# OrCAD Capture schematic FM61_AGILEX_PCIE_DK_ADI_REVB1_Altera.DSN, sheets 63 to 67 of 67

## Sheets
63 PWR - 2p5V: size B
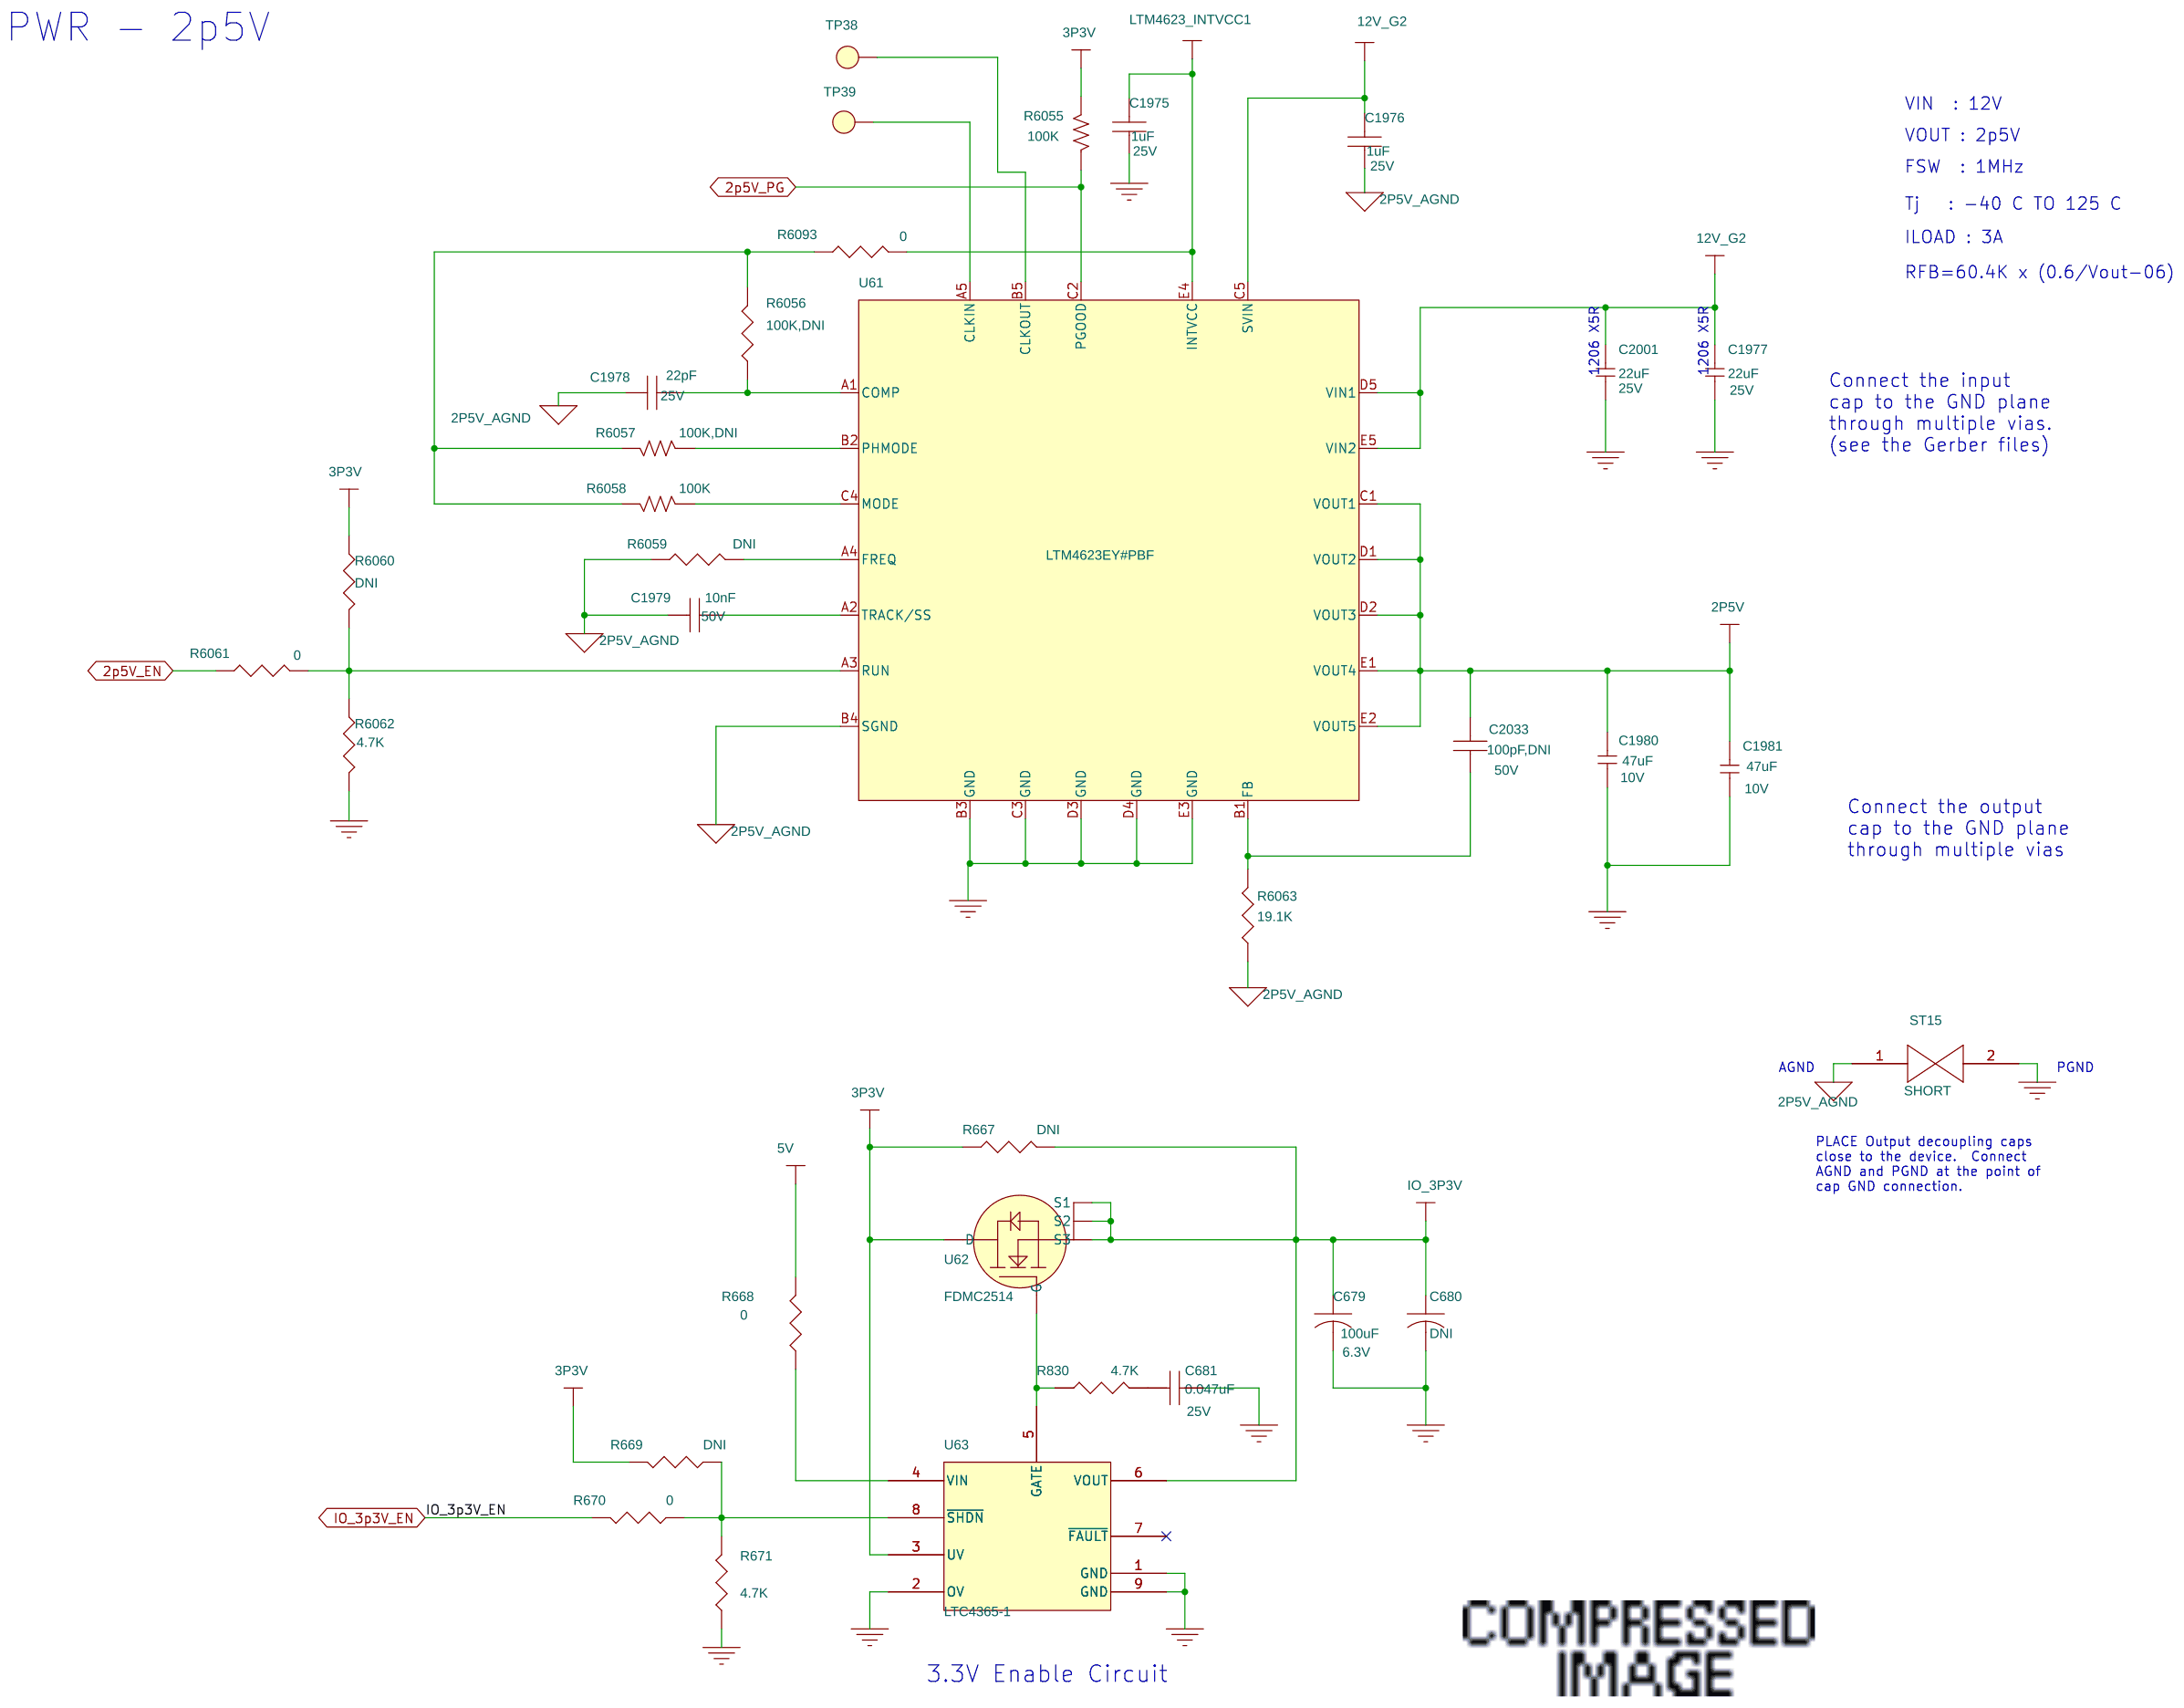
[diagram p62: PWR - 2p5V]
64 PWR - 1p1V_VCCH_GXER1: size Custom
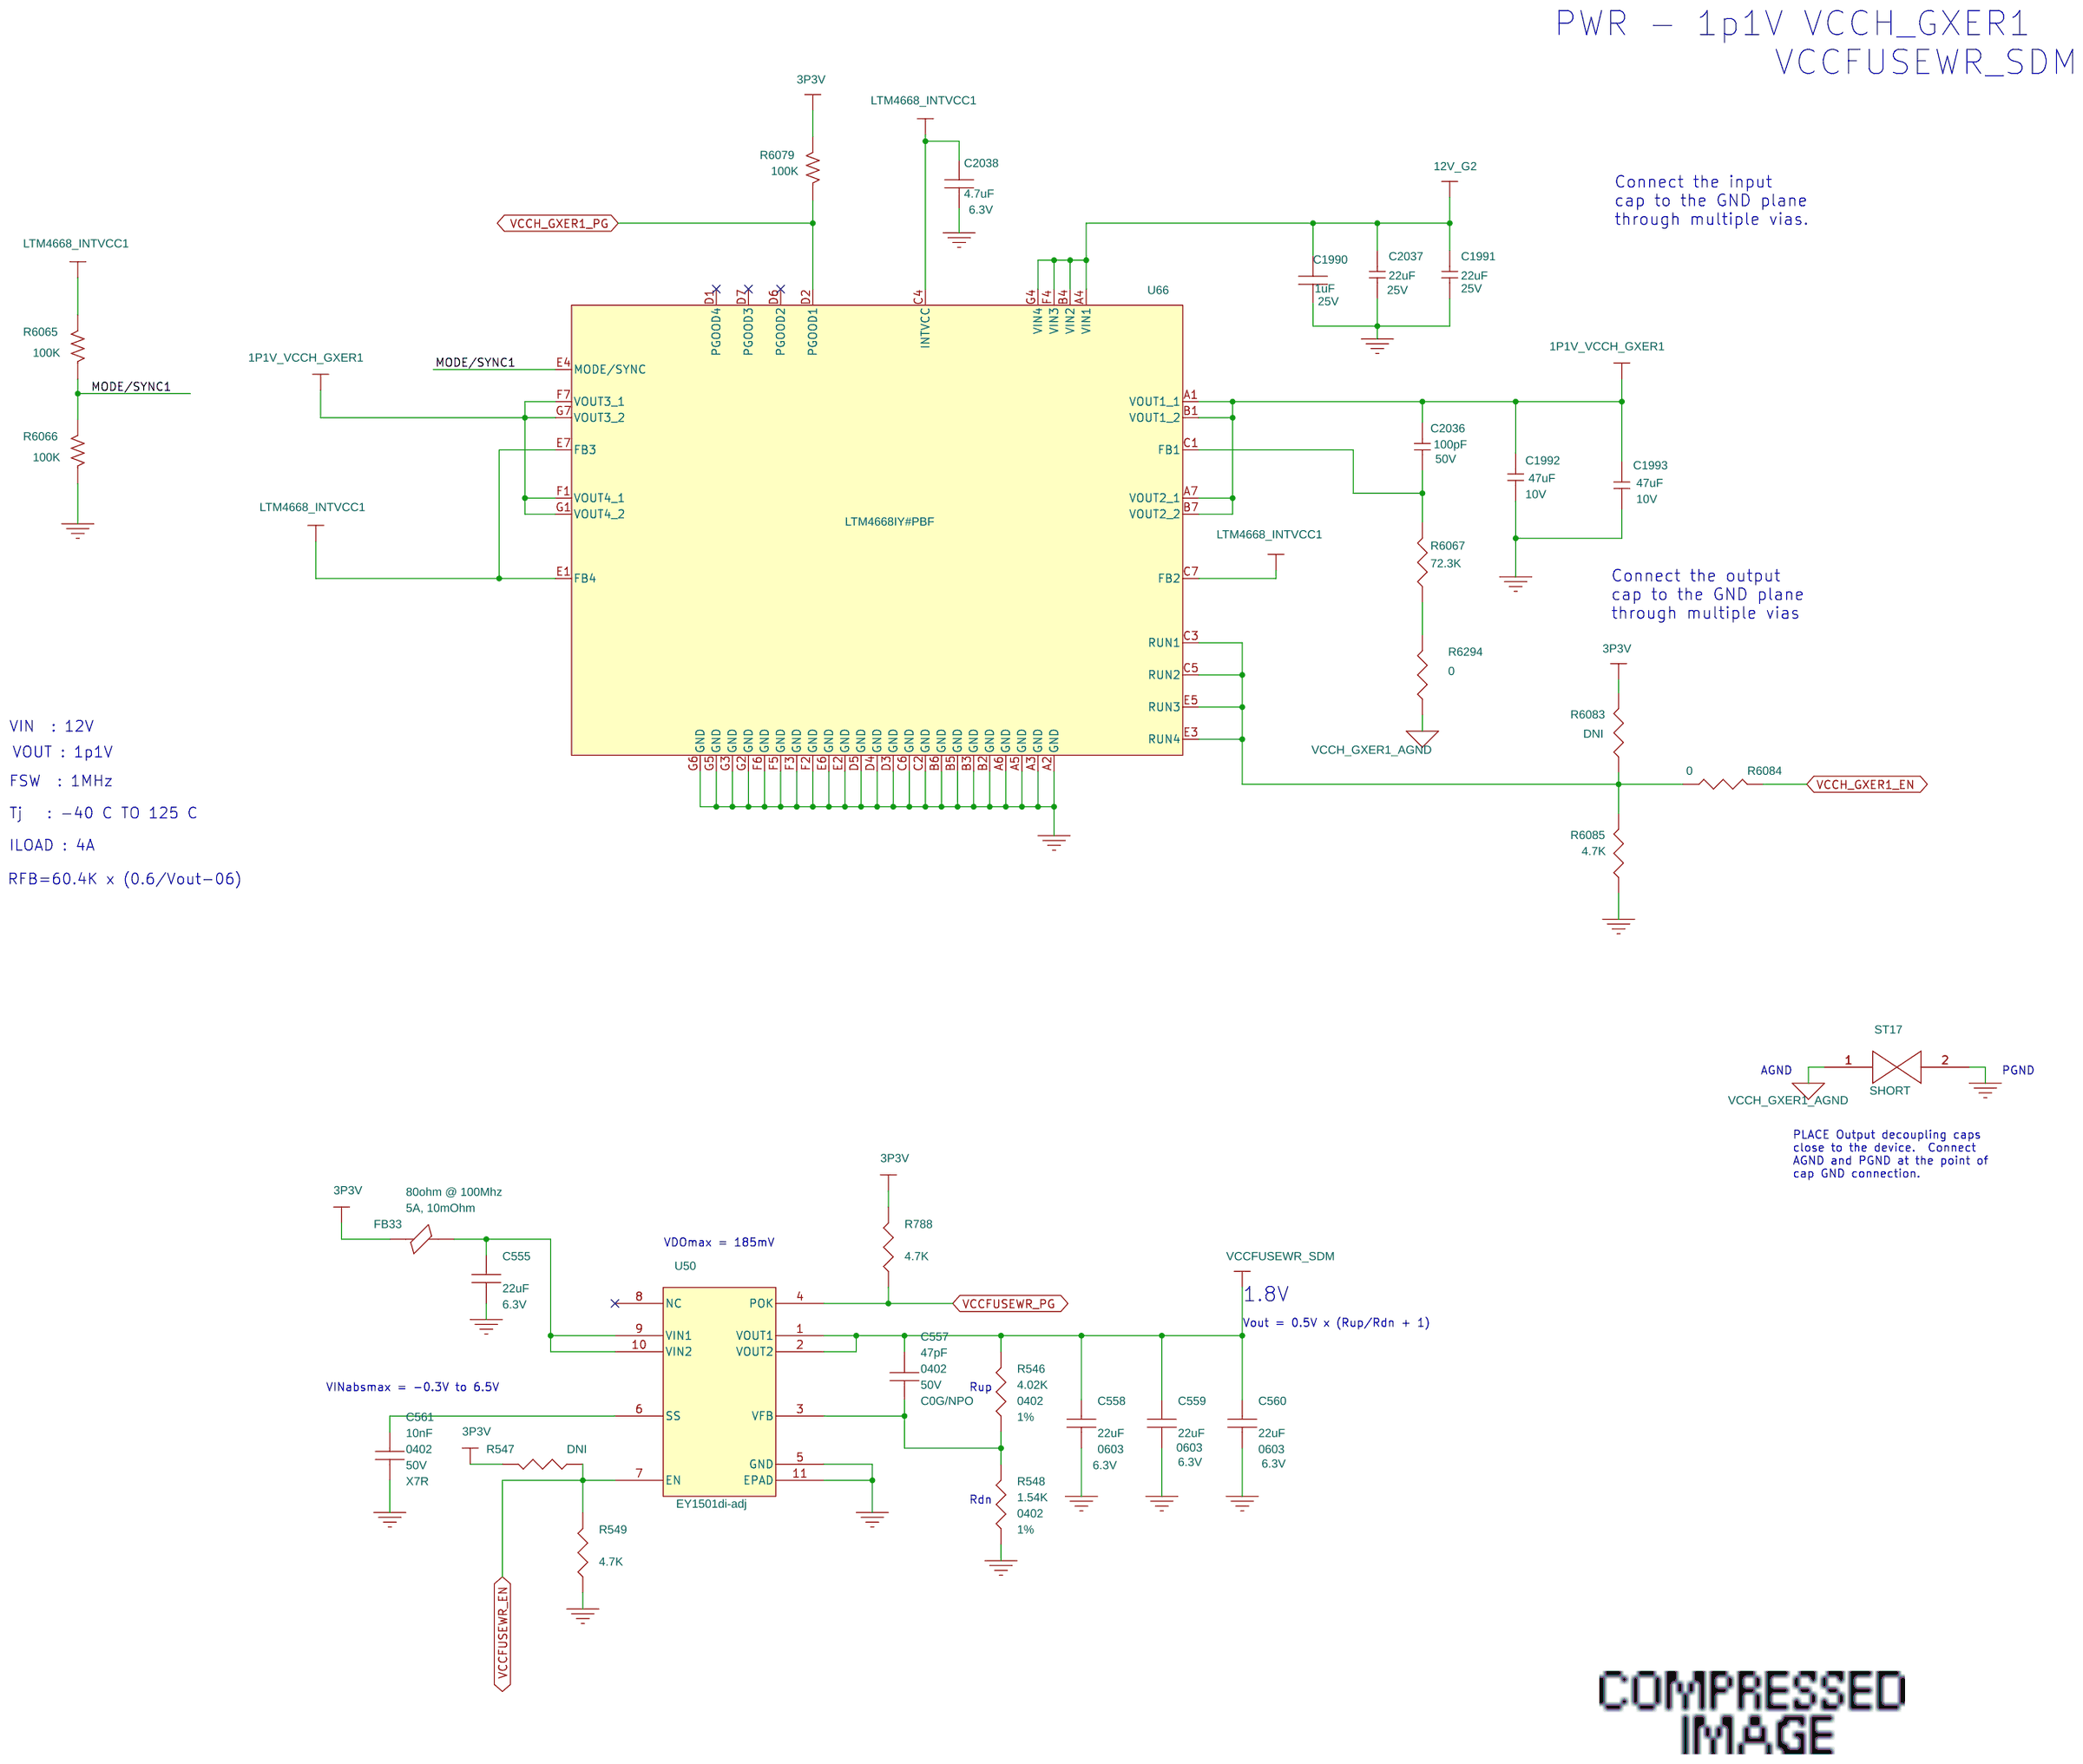
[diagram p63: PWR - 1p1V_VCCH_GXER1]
65 Decoupling Caps 1: size B
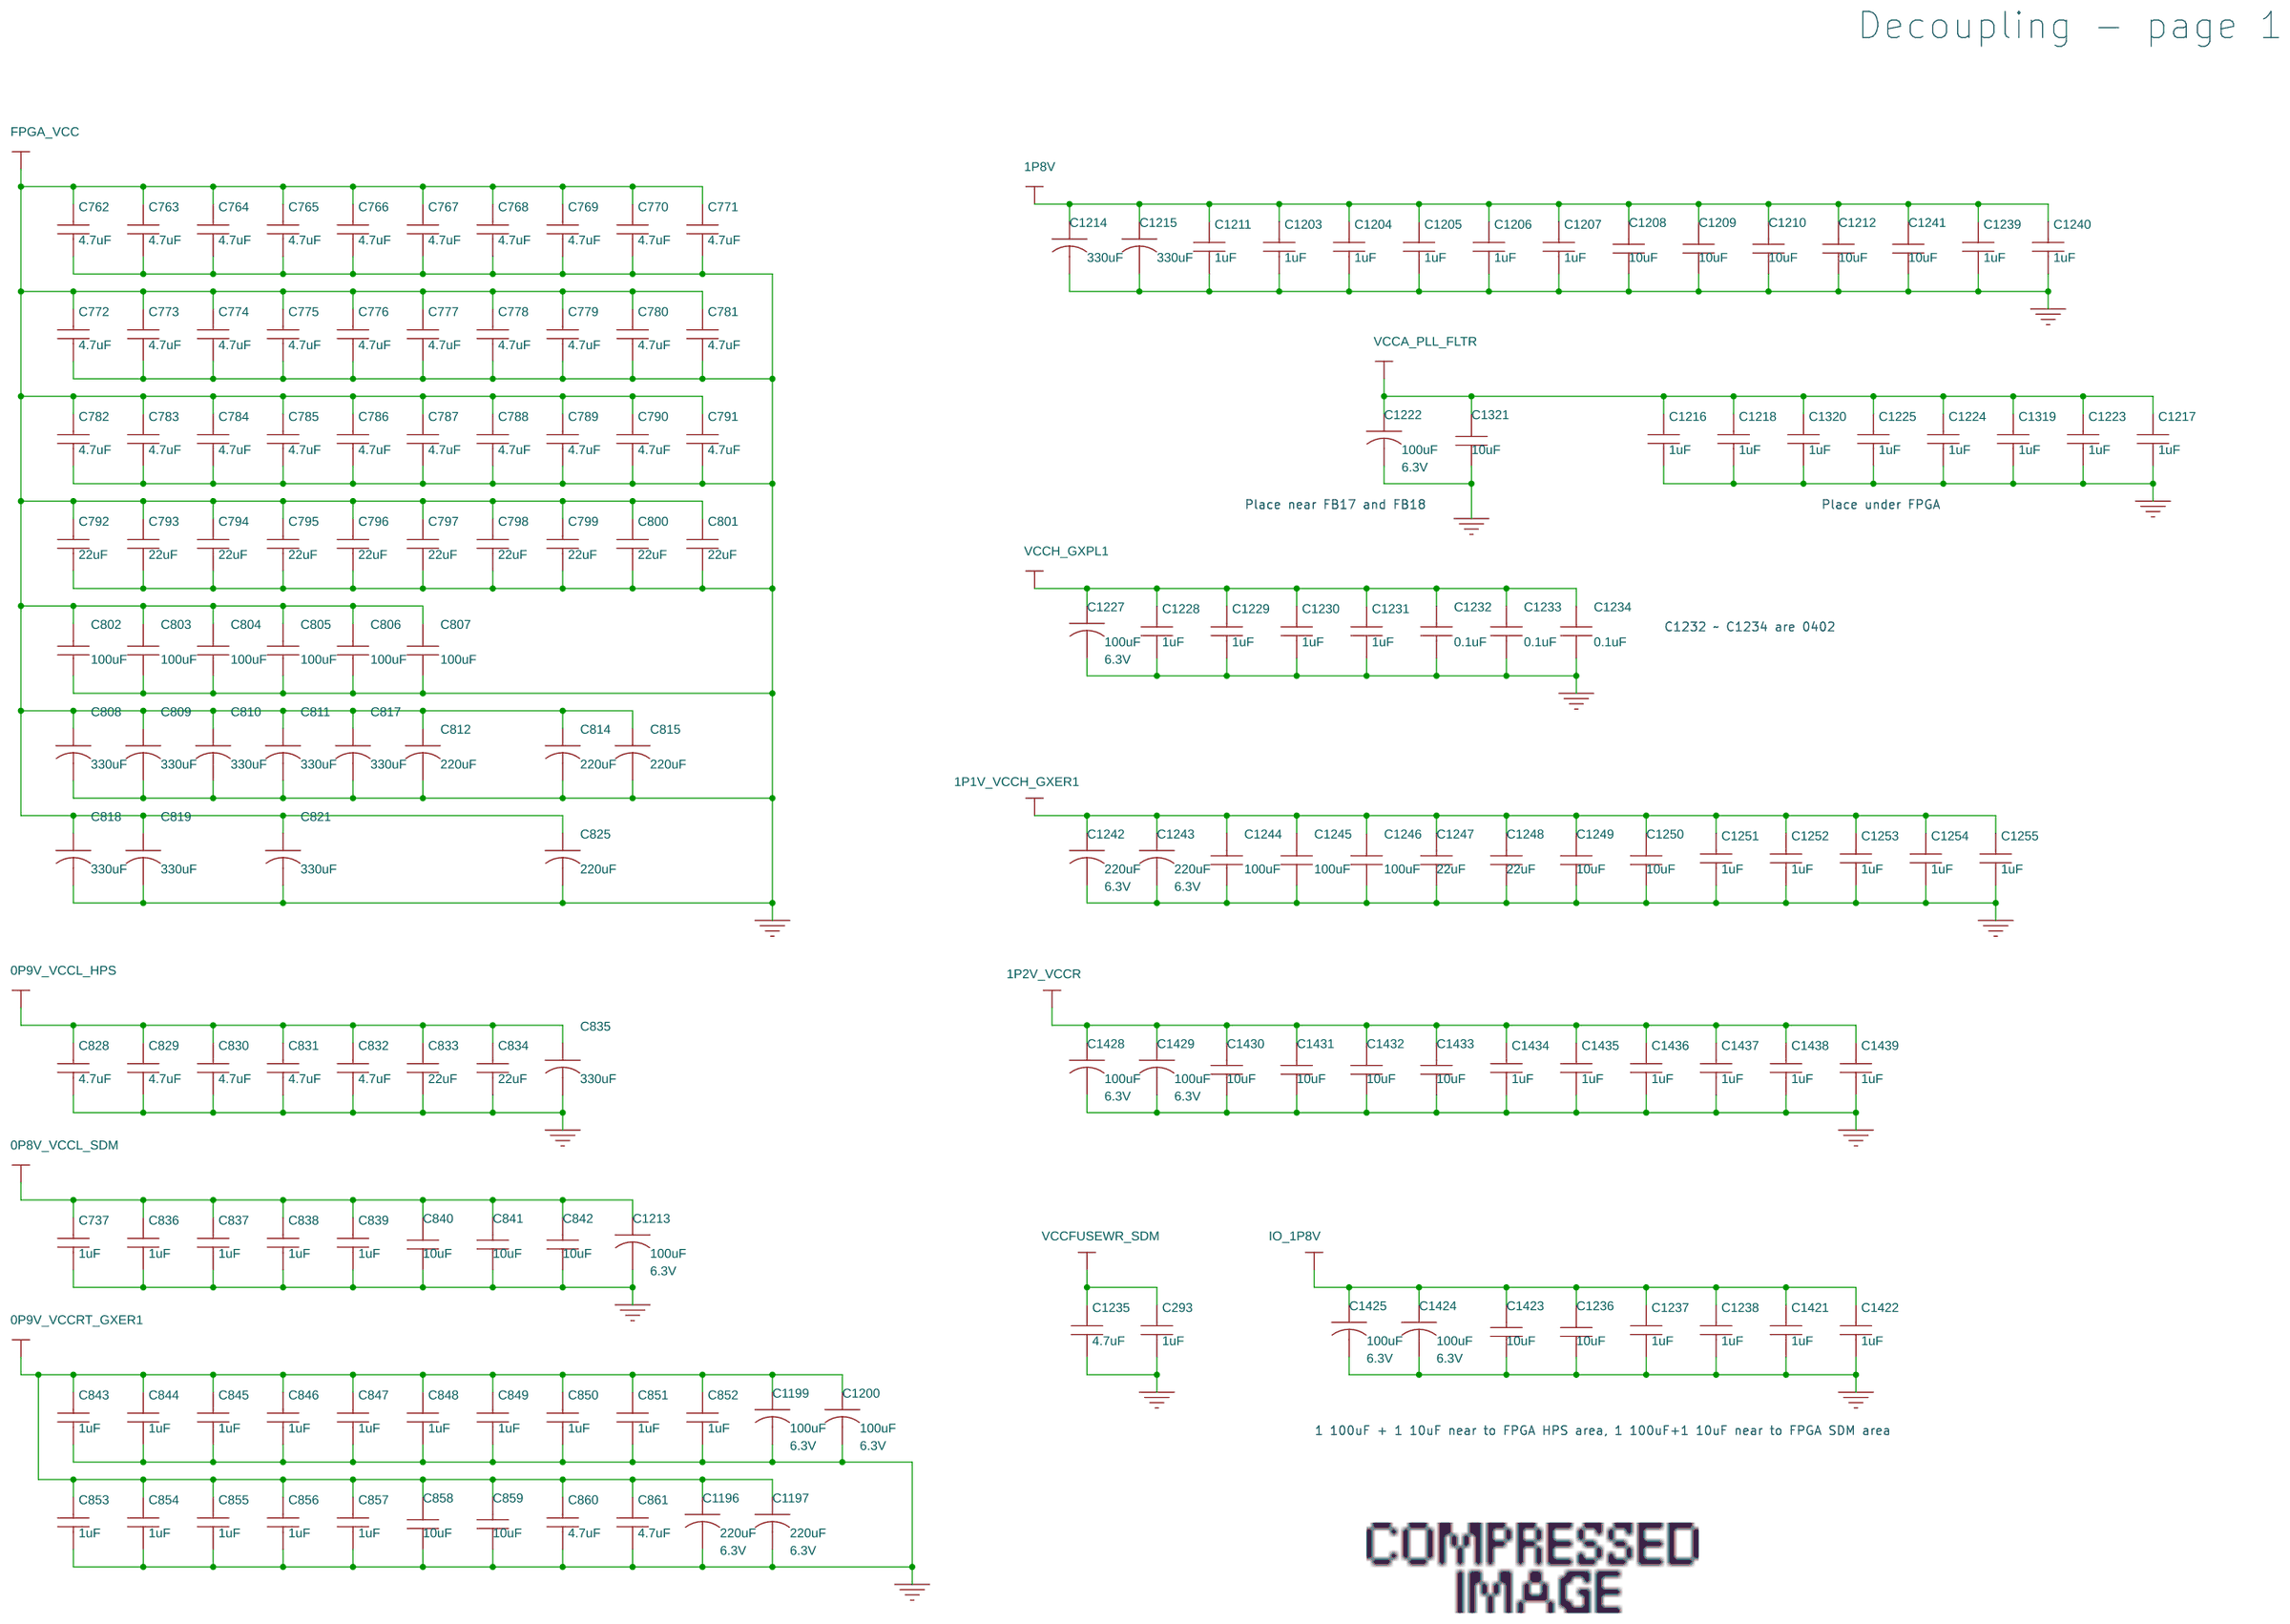
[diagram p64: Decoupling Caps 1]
66 Decoupling Caps 2: size B
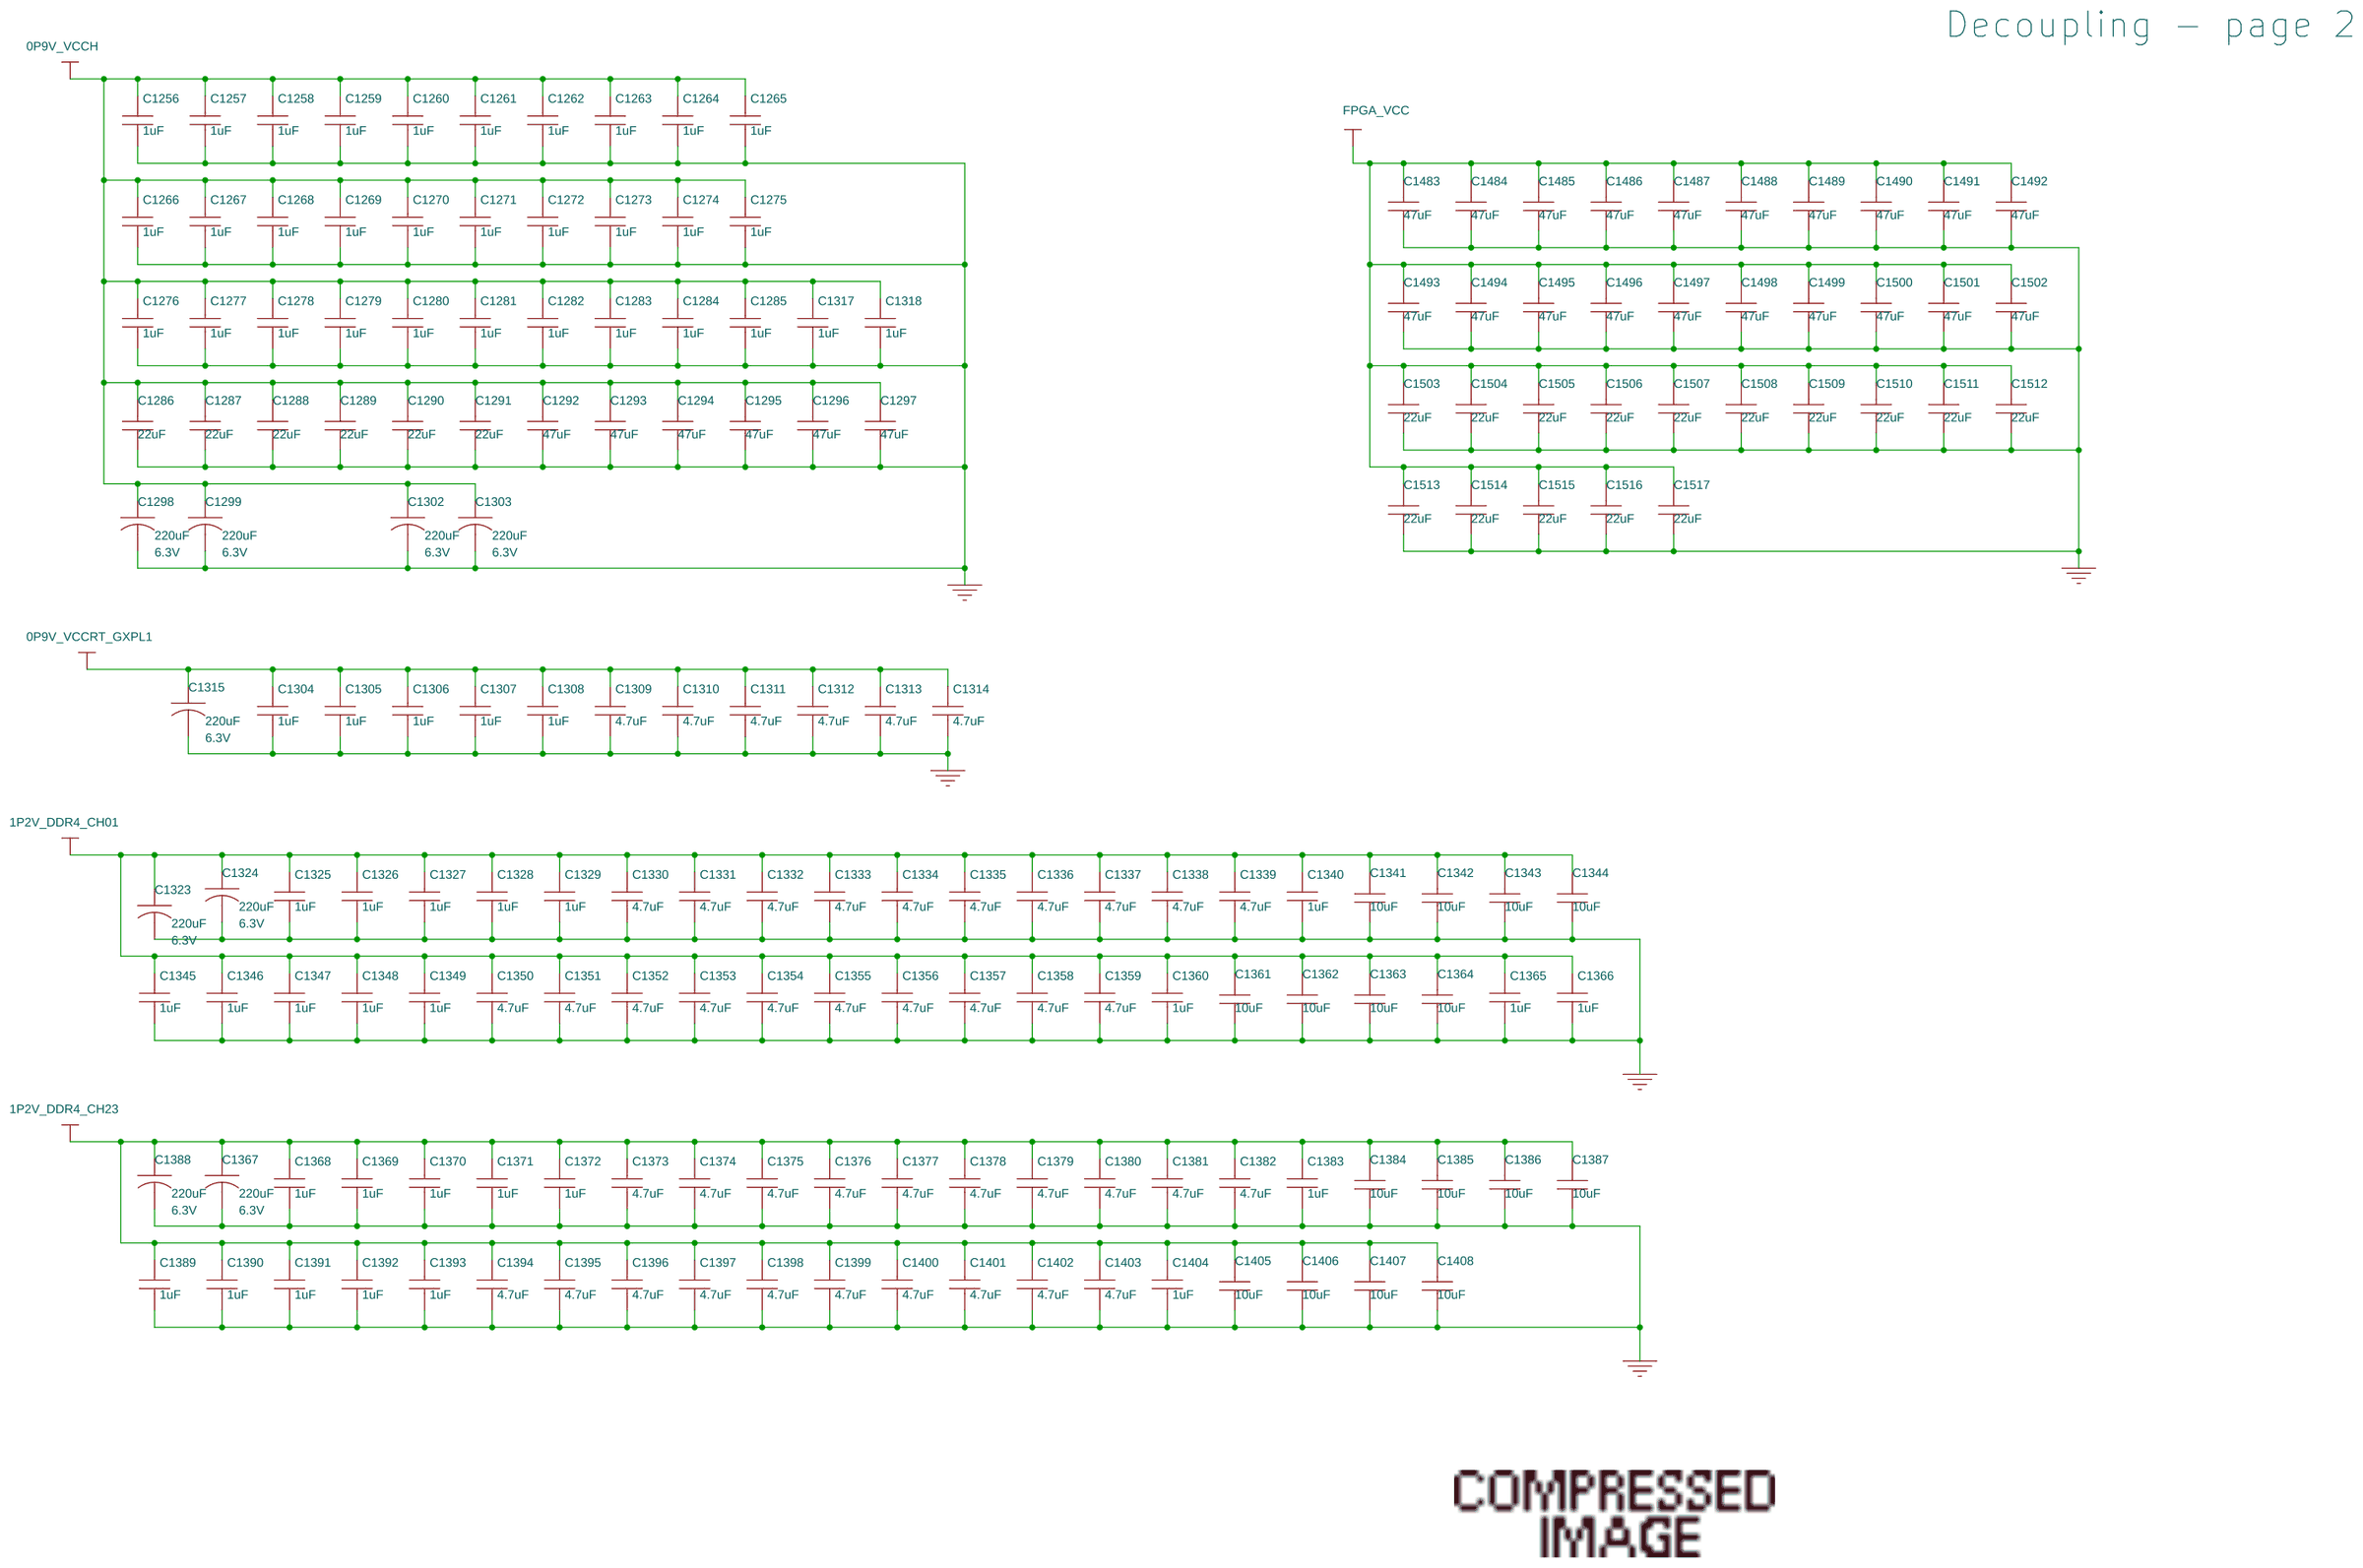
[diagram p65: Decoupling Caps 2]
67 REVISION HISTORY
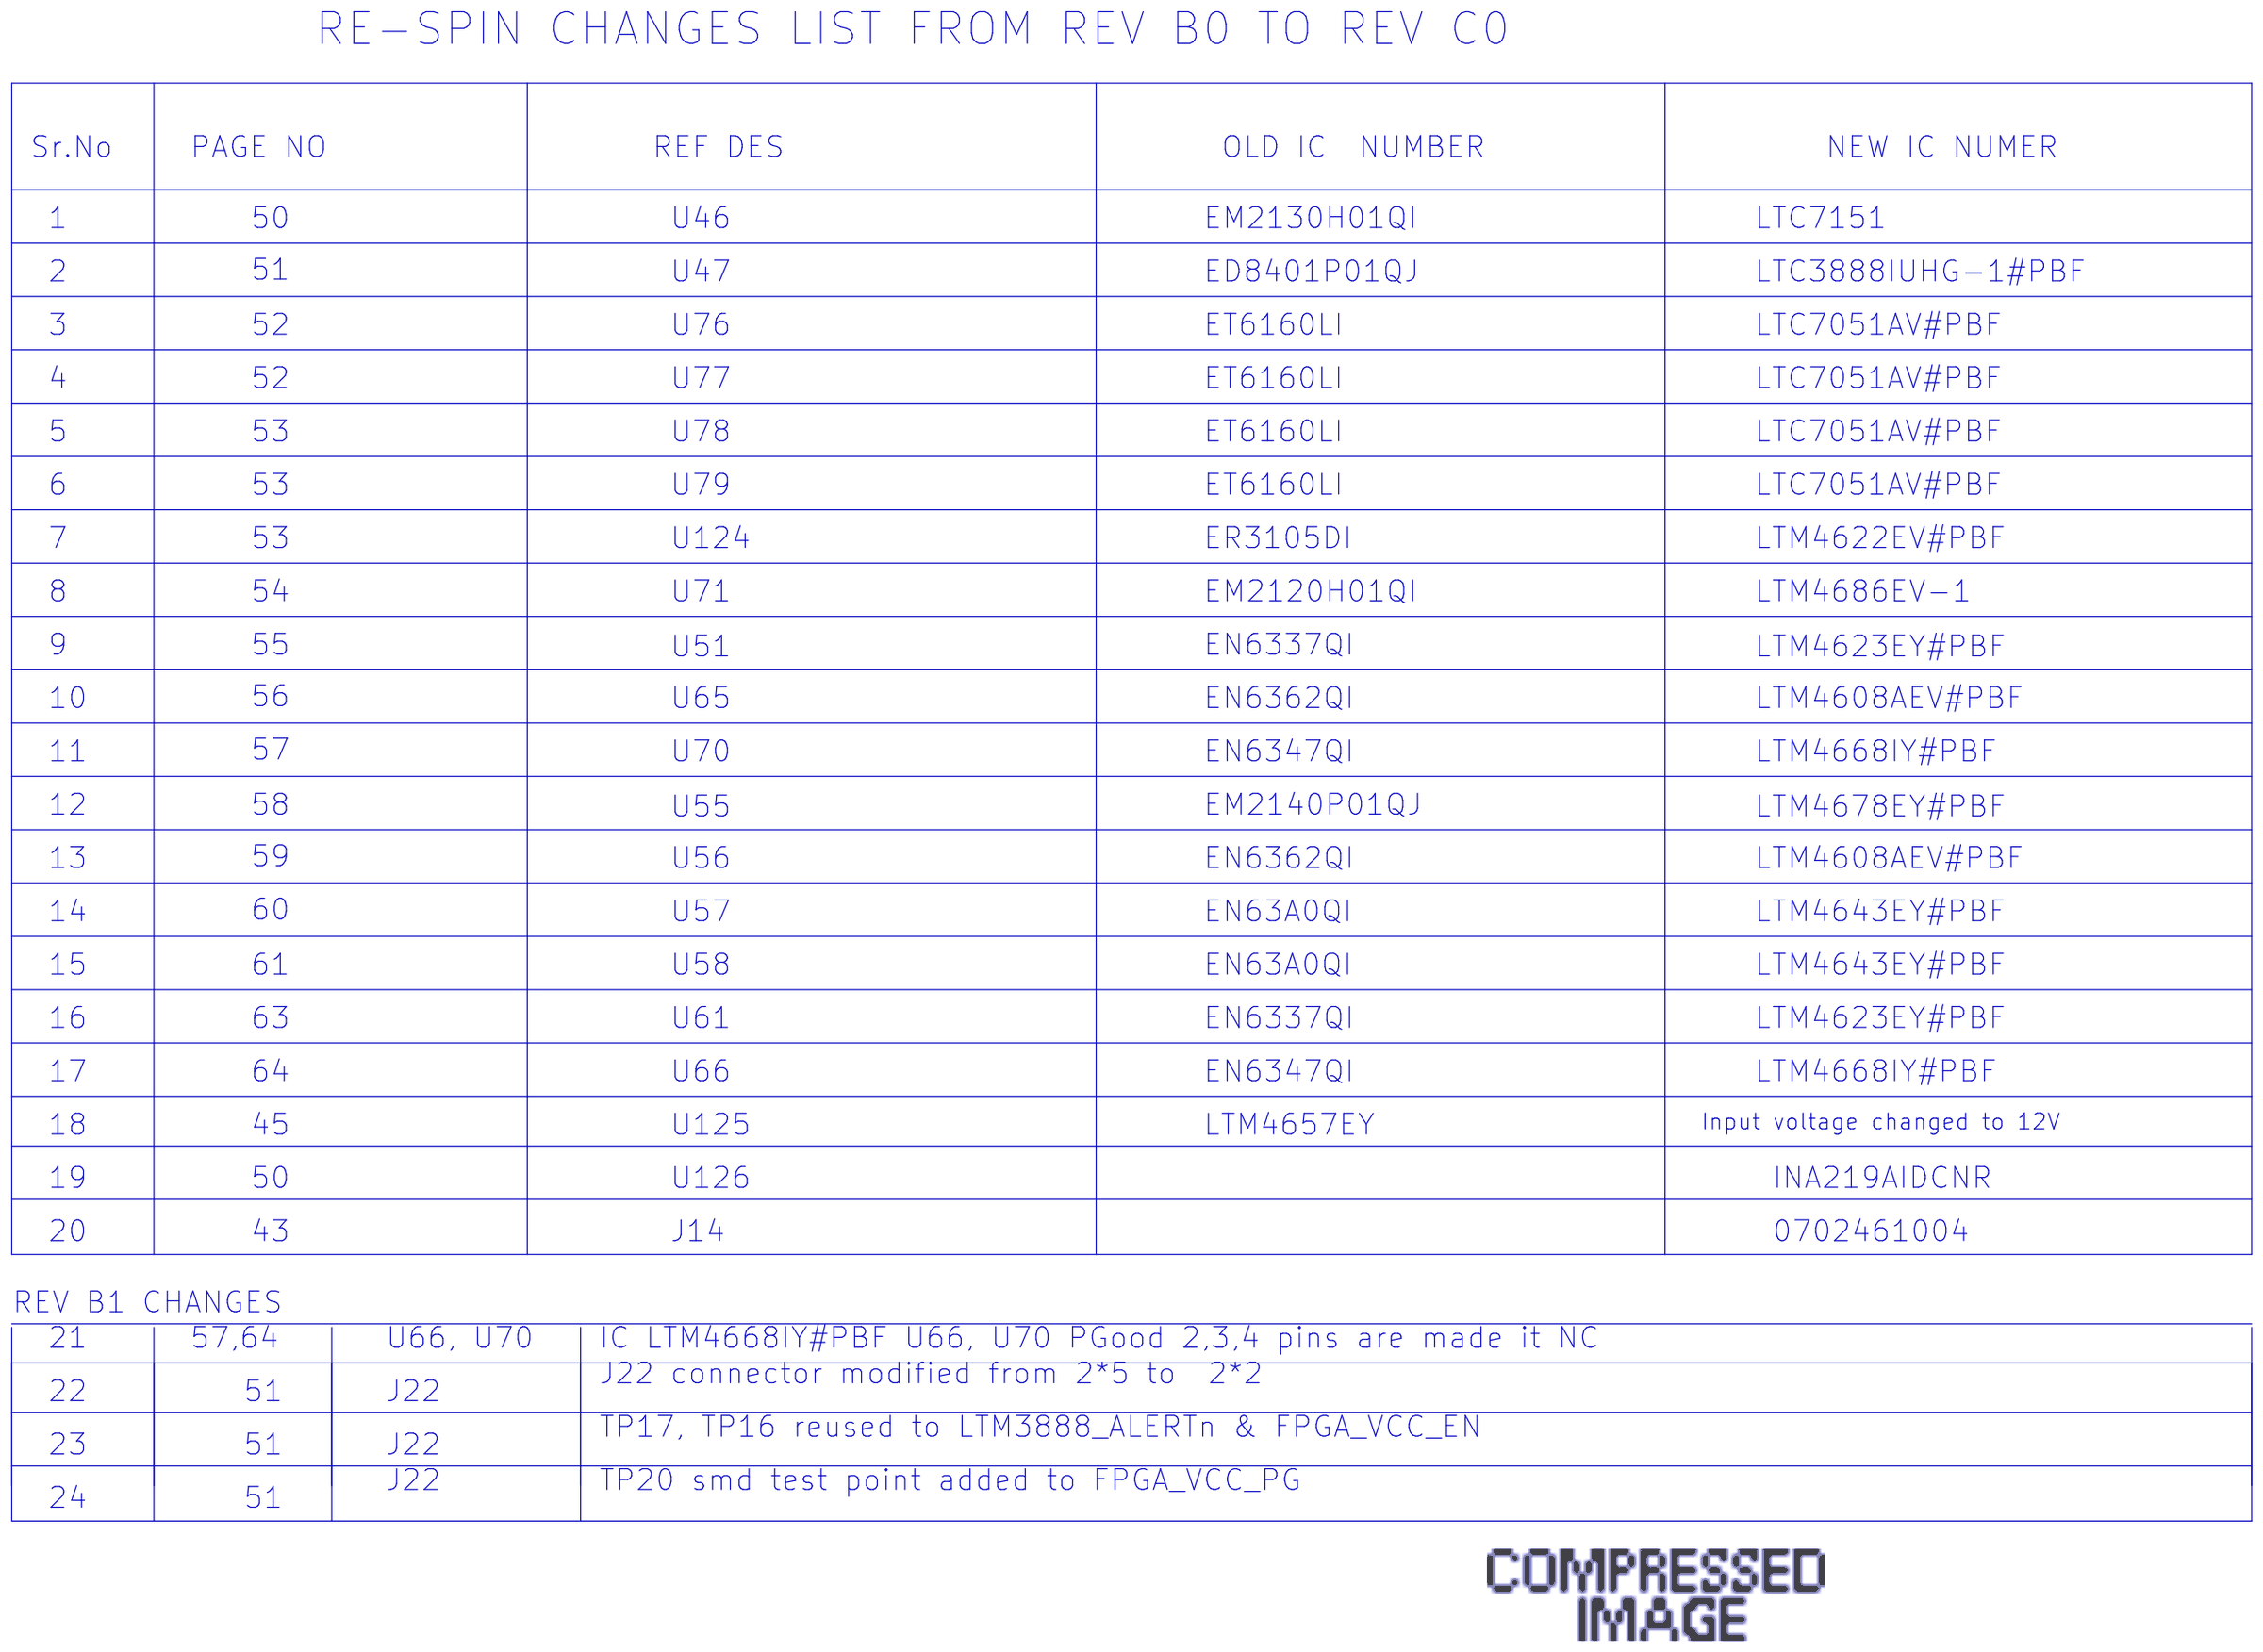
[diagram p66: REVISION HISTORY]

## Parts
sheet Decoupling Caps 1
C293  1uF  [0201]
C737  1uF  [0201]
C762  4.7uF  [0402]
C763  4.7uF  [0402]
C764  4.7uF  [0402]
C765  4.7uF  [0402]
C766  4.7uF  [0402]
C767  4.7uF  [0402]
C768  4.7uF  [0402]
C769  4.7uF  [0402]
C770  4.7uF  [0402]
C771  4.7uF  [0402]
C772  4.7uF  [0402]
C773  4.7uF  [0402]
C774  4.7uF  [0402]
C775  4.7uF  [0402]
C776  4.7uF  [0402]
C777  4.7uF  [0402]
C778  4.7uF  [0402]
C779  4.7uF  [0402]
C780  4.7uF  [0402]
C781  4.7uF  [0402]
C782  4.7uF  [0402]
C783  4.7uF  [0402]
C784  4.7uF  [0402]
C785  4.7uF  [0402]
C786  4.7uF  [0402]
C787  4.7uF  [0402]
C788  4.7uF  [0402]
C789  4.7uF  [0402]
C790  4.7uF  [0402]
C791  4.7uF  [0402]
C792  22uF  [0805]
C793  22uF  [0805]
C794  22uF  [0805]
C795  22uF  [0805]
C796  22uF  [0805]
C797  22uF  [0805]
C798  22uF  [0805]
C799  22uF  [0805]
C800  22uF  [0805]
C801  22uF  [0805]
C802  100uF  [1206]
C803  100uF  [1206]
C804  100uF  [1206]
C805  100uF  [1206]
C806  100uF  [1206]
C807  100uF  [1206]
C808  330uF  [1411]
C809  330uF  [1411]
C810  330uF  [1411]
C811  330uF  [1411]
C812  220uF  [1411]
C814  220uF  [1411]
C815  220uF  [1411]
C817  330uF  [1411]
C818  330uF  [1411]
C819  330uF  [1411]
C821  330uF  [1411]
C825  220uF  [1411]
C828  4.7uF  [0402]
C829  4.7uF  [0402]
C830  4.7uF  [0402]
C831  4.7uF  [0402]
C832  4.7uF  [0402]
C833  22uF  [0805]
C834  22uF  [0805]
C835  330uF  [1411]
C836  1uF  [0201]
C837  1uF  [0201]
C838  1uF  [0201]
C839  1uF  [0201]
C840  10uF  [0603]
C841  10uF  [0603]
C842  10uF  [0603]
C843  1uF  [0201]
C844  1uF  [0201]
C845  1uF  [0201]
C846  1uF  [0201]
C847  1uF  [0201]
C848  1uF  [0201]
C849  1uF  [0201]
C850  1uF  [0201]
C851  1uF  [0201]
C852  1uF  [0201]
C853  1uF  [0201]
C854  1uF  [0201]
C855  1uF  [0201]
C856  1uF  [0201]
C857  1uF  [0201]
C858  10uF  [0603]
C859  10uF  [0603]
C860  4.7uF  [0603]
C861  4.7uF  [0603]
C1196  220uF  [D2E]
C1197  220uF  [D2E]
C1199  100uF  [B2]
C1200  100uF  [B2]
C1203  1uF  [0201]
C1204  1uF  [0201]
C1205  1uF  [0201]
C1206  1uF  [0201]
C1207  1uF  [0201]
C1208  10uF  [0603]
C1209  10uF  [0603]
C1210  10uF  [0603]
C1211  1uF  [0201]
C1212  10uF  [0603]
C1213  100uF  [B2]
C1214  330uF  [1411]
C1215  330uF  [1411]
C1216  1uF  [0201]
C1217  1uF  [0201]
C1218  1uF  [0201]
C1222  100uF  [B2]
C1223  1uF  [0201]
C1224  1uF  [0201]
C1225  1uF  [0201]
C1227  100uF  [B2]
C1228  1uF  [0201]
C1229  1uF  [0201]
C1230  1uF  [0201]
C1231  1uF  [0201]
C1232  0.1uF  [0402]
C1233  0.1uF  [0402]
C1234  0.1uF  [0402]
C1235  4.7uF  [0402]
C1236  10uF  [0603]
C1237  1uF  [0201]
C1238  1uF  [0201]
C1239  1uF  [0201]
C1240  1uF  [0201]
C1241  10uF  [0603]
C1242  220uF  [D2E]
C1243  220uF  [D2E]
C1244  100uF  [0805]
C1245  100uF  [0805]
C1246  100uF  [0805]
C1247  22uF  [0603]
C1248  22uF  [0603]
C1249  10uF  [0402]
C1250  10uF  [0402]
C1251  1uF  [0201]
C1252  1uF  [0201]
C1253  1uF  [0201]
C1254  1uF  [0201]
C1255  1uF  [0201]
C1319  1uF  [0201]
C1320  1uF  [0201]
C1321  10uF  [0603]
C1421  1uF  [0201]
C1422  1uF  [0201]
C1423  10uF  [0603]
C1424  100uF  [B2]
C1425  100uF  [B2]
C1428  100uF  [B2]
C1429  100uF  [B2]
C1430  10uF  [0603]
C1431  10uF  [0603]
C1432  10uF  [0603]
C1433  10uF  [0603]
C1434  1uF  [0201]
C1435  1uF  [0201]
C1436  1uF  [0201]
C1437  1uF  [0201]
C1438  1uF  [0201]
C1439  1uF  [0201]
sheet Decoupling Caps 2
C1256  1uF  [0201]
C1257  1uF  [0201]
C1258  1uF  [0201]
C1259  1uF  [0201]
C1260  1uF  [0201]
C1261  1uF  [0201]
C1262  1uF  [0201]
C1263  1uF  [0201]
C1264  1uF  [0201]
C1265  1uF  [0201]
C1266  1uF  [0201]
C1267  1uF  [0201]
C1268  1uF  [0201]
C1269  1uF  [0201]
C1270  1uF  [0201]
C1271  1uF  [0201]
C1272  1uF  [0201]
C1273  1uF  [0201]
C1274  1uF  [0201]
C1275  1uF  [0201]
C1276  1uF  [0201]
C1277  1uF  [0201]
C1278  1uF  [0201]
C1279  1uF  [0201]
C1280  1uF  [0201]
C1281  1uF  [0201]
C1282  1uF  [0201]
C1283  1uF  [0201]
C1284  1uF  [0201]
C1285  1uF  [0201]
C1286  22uF  [0603]
C1287  22uF  [0603]
C1288  22uF  [0603]
C1289  22uF  [0603]
C1290  22uF  [0603]
C1291  22uF  [0603]
C1292  47uF  [0805]
C1293  47uF  [0805]
C1294  47uF  [0805]
C1295  47uF  [0805]
C1296  47uF  [0805]
C1297  47uF  [0805]
C1298  220uF  [D2E]
C1299  220uF  [D2E]
C1302  220uF  [D2E]
C1303  220uF  [D2E]
C1304  1uF  [0201]
C1305  1uF  [0201]
C1306  1uF  [0201]
C1307  1uF  [0201]
C1308  1uF  [0201]
C1309  4.7uF  [0201]
C1310  4.7uF  [0201]
C1311  4.7uF  [0201]
C1312  4.7uF  [0201]
C1313  4.7uF  [0201]
C1314  4.7uF  [0201]
C1315  220uF  [D2E]
C1317  1uF  [0201]
C1318  1uF  [0201]
C1323  220uF  [D2E]
C1324  220uF  [D2E]
C1325  1uF  [0201]
C1326  1uF  [0201]
C1327  1uF  [0201]
C1328  1uF  [0201]
C1329  1uF  [0201]
C1330  4.7uF  [0201]
C1331  4.7uF  [0201]
C1332  4.7uF  [0201]
C1333  4.7uF  [0201]
C1334  4.7uF  [0201]
C1335  4.7uF  [0201]
C1336  4.7uF  [0201]
C1337  4.7uF  [0201]
C1338  4.7uF  [0201]
C1339  4.7uF  [0201]
C1340  1uF  [0201]
C1341  10uF  [0603]
C1342  10uF  [0603]
C1343  10uF  [0603]
C1344  10uF  [0603]
C1345  1uF  [0201]
C1346  1uF  [0201]
C1347  1uF  [0201]
C1348  1uF  [0201]
C1349  1uF  [0201]
C1350  4.7uF  [0201]
C1351  4.7uF  [0201]
C1352  4.7uF  [0201]
C1353  4.7uF  [0201]
C1354  4.7uF  [0201]
C1355  4.7uF  [0201]
C1356  4.7uF  [0201]
C1357  4.7uF  [0201]
C1358  4.7uF  [0201]
C1359  4.7uF  [0201]
C1360  1uF  [0201]
C1361  10uF  [0603]
C1362  10uF  [0603]
C1363  10uF  [0603]
C1364  10uF  [0603]
C1365  1uF  [0201]
C1366  1uF  [0201]
C1367  220uF  [D2E]
C1368  1uF  [0201]
C1369  1uF  [0201]
C1370  1uF  [0201]
C1371  1uF  [0201]
C1372  1uF  [0201]
C1373  4.7uF  [0201]
C1374  4.7uF  [0201]
C1375  4.7uF  [0201]
C1376  4.7uF  [0201]
C1377  4.7uF  [0201]
C1378  4.7uF  [0201]
C1379  4.7uF  [0201]
C1380  4.7uF  [0201]
C1381  4.7uF  [0201]
C1382  4.7uF  [0201]
C1383  1uF  [0201]
C1384  10uF  [0603]
C1385  10uF  [0603]
C1386  10uF  [0603]
C1387  10uF  [0603]
C1388  220uF  [D2E]
C1389  1uF  [0201]
C1390  1uF  [0201]
C1391  1uF  [0201]
C1392  1uF  [0201]
C1393  1uF  [0201]
C1394  4.7uF  [0201]
C1395  4.7uF  [0201]
C1396  4.7uF  [0201]
C1397  4.7uF  [0201]
C1398  4.7uF  [0201]
C1399  4.7uF  [0201]
C1400  4.7uF  [0201]
C1401  4.7uF  [0201]
C1402  4.7uF  [0201]
C1403  4.7uF  [0201]
C1404  1uF  [0201]
C1405  10uF  [0603]
C1406  10uF  [0603]
C1407  10uF  [0603]
C1408  10uF  [0603]
C1483  47uF  [0805]
C1484  47uF  [0805]
C1485  47uF  [0805]
C1486  47uF  [0805]
C1487  47uF  [0805]
C1488  47uF  [0805]
C1489  47uF  [0805]
C1490  47uF  [0805]
C1491  47uF  [0805]
C1492  47uF  [0805]
C1493  47uF  [0805]
C1494  47uF  [0805]
C1495  47uF  [0805]
C1496  47uF  [0805]
C1497  47uF  [0805]
C1498  47uF  [0805]
C1499  47uF  [0805]
C1500  47uF  [0805]
C1501  47uF  [0805]
C1502  47uF  [0805]
C1503  22uF  [0603]
C1504  22uF  [0603]
C1505  22uF  [0603]
C1506  22uF  [0603]
C1507  22uF  [0603]
C1508  22uF  [0603]
C1509  22uF  [0603]
C1510  22uF  [0603]
C1511  22uF  [0603]
C1512  22uF  [0603]
C1513  22uF  [0603]
C1514  22uF  [0603]
C1515  22uF  [0603]
C1516  22uF  [0603]
C1517  22uF  [0603]
sheet PWR - 1p1V_VCCH_GXER1
C555  22uF  [0603]
C557  47pF  [0402]
C558  22uF  [0603]
C559  22uF  [0603]
C560  22uF  [0603]
C561  10nF  [0402]
C1990  1uF  [0402]
C1991  22uF  [1206]
C1992  47uF  [C1206]
C1993  47uF  [C1206]
C2036  100pF  [0402]
C2037  22uF  [1206]
C2038  4.7uF  [0402]
FB33  80ohm @ 100Mhz  [0805]
R546  4.02K  [0402]
R547  DNI  [0402]
R548  1.54K  [0402]
R549  4.7K  [0402]
R788  4.7K  [0402]
R6065  100K  [R0402]
R6066  100K  [R0402]
R6067  72.3K  [0402]
R6079  100K  [R0402]
R6083  DNI  [0402]
R6084  0  [0402]
R6085  4.7K  [0402]
R6294  0  [0402]
ST17  SHORT  [SHORT]
U50  EY1501di-adj  [DFN-11]
U66  LTM4668IY#PBF  [BGA49C80P7X7_625X625X230N]
sheet PWR - 2p5V
C679  100uF  [B2]
C680  DNI  [1210]
C681  0.047uF  [0402]
C1975  1uF  [0402]
C1976  1uF  [0402]
C1977  22uF  [1206]
C1978  22pF  [0402]
C1979  10nF  [0402]
C1980  47uF  [C1206]
C1981  47uF  [C1206]
C2001  22uF  [1206]
C2033  100pF,DNI  [0402]
R667  DNI  [1206]
R668  0  [0402]
R669  DNI  [0402]
R670  0  [0402]
R671  4.7K  [0402]
R830  4.7K  [0402]
R6055  100K  [R0402]
R6056  100K,DNI  [0402]
R6057  100K,DNI  [R0402]
R6058  100K  [R0402]
R6059  DNI  [0402]
R6060  DNI  [0402]
R6061  0  [0402]
R6062  4.7K  [0402]
R6063  19.1K  [0402]
R6093  0  [0402]
ST15  SHORT  [SHORT]
TP38  TP, 0.016", Thru Hole  [30MIL_TP]
TP39  TP, 0.016", Thru Hole  [30MIL_TP]
U61  LTM4623EY#PBF  [BGA25C127P5X5_625X625X262]
U62  FDMC2514  [FDMC8878_VER2]
U63  LTC4365-1  [DFN8-EPAD_3X2]

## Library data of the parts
C293 C737 C836-C839 C843-C857 C1203-C1207 C1211 C1216-C1218 C1223-C1225 C1228-C1231 C1237-C1240 C1251-C1285 C1304-C1308 C1317-C1320 C1325-C1329 C1340 C1345-C1349 C1360 C1365 C1366 C1368-C1372 C1383 C1389-C1393 C1404 C1421 C1422 C1434-C1439 = CAP: CAP - CER 1UF 6.3V 20% X5R 0201; IPN: C83410-013; Item Num: P03-17777R; Lead Free Status: Yes; Manufacturer: TDK; Manufacturer Part Num: C0603X5R0J105M; Num Pins: 2; Part Class: CAPACITORS; RoHS Compliant: Yes
C762-C791 C828-C832 C1235 = CAP: CAP - CER 4.7UF, +/-20%, 6.3V, X5R, 0402; AGILE_LINK: http://sj-agile9app/Agile/PLMServlet?action=OpenEmailObject&classid=10000&objid=257560276; IPN: H68701-001; Item Num: P03-17432R; LIFECYCLE_PHASE: Active; Lead Free Status: Not Lead Free; MFR_LIFECYCLE: Active; Manufacturer: Murata; Manufacturer Part Num: GRM155R60J475ME87D; Num Pins: 2; PART_SUBCLASS: CAPACITORS; RATED_VOLTAGE: 6.3V; RoHS Compliant: RoHS Compliant; TOLERANCE: +/-10%
C792-C801 C833 C834 = CAP: CAP - CER, 22UF, 16V, 20%, X5R, 0805; AGILE_LINK: http://sj-agile9app/Agile/PLMServlet?action=OpenEmailObject&classid=10000&objid=257560276; IPN: H14974-002; Item Num: P03-17664R; LIFECYCLE_PHASE: Active; Lead Free Status: Not Lead Free; MFR_LIFECYCLE: Active; Manufacturer: TDK Electronics; Manufacturer Part Num: GRM21BR61C226ME44L; Num Pins: 2; PART_SUBCLASS: CAPACITORS; RATED_VOLTAGE: 16V; RoHS Compliant: RoHS Compliant; TOLERANCE: +/-10%
C802-C807 = CAP: CAP CER 100UF 6.3V X6T 1206; AGILE_LINK: http://sj-agile9app/Agile/PLMServlet?action=OpenEmailObject&classid=10000&objid=257560276; IPN: H65271-004; Item Num: P03-18002R; LIFECYCLE_PHASE: Active; Lead Free Status: Lead Free; MFR_LIFECYCLE: Active; Manufacturer: Murata; Manufacturer Part Num: GRM31CD80J107ME39L; Num Pins: 2; PART_SUBCLASS: CAPACITORS; RATED_VOLTAGE: 6.3V; RoHS Compliant: RoHS Compliant; TOLERANCE: 20%; Temperature Coefficient: X6T
C808-C811 C817-C819 C821 C835 C1214 C1215 = PCAP: CAP TANT POLY 330UF 2.5V (1411) 3528 metric; AGILE_LINK: http://sj-agile9app/Agile/PLMServlet?action=OpenEmailObject&classid=10000&objid=257237054; IPN: K21348-001; Item Num: P03-17992R; LIFECYCLE_PHASE: Active; Lead Free Status: Lead Free; MFR_LIFECYCLE: Active; Manufacturer: Vishay Sprague; Manufacturer Part Num: T55B337M2R5C0035; Num Pins: 2; PART_SUBCLASS: CAPACITORS; RATED_VOLTAGE: 2.5V; RoHS Compliant: RoHS Compliant; TOLERANCE: 20%; Type: Tant Poly
C812 C814 C815 C825 = PCAP: CAP TANT POLY 220UF 2.5V (1411) 3528 metric; AGILE_LINK: http://sj-agile9app/Agile/PLMServlet?action=OpenEmailObject&classid=10000&objid=257237054; IPN: K21349-001; Item Num: P03-17997R; LIFECYCLE_PHASE: Active; Lead Free Status: Lead Free; MFR_LIFECYCLE: Active; Manufacturer: Kemet; Manufacturer Part Num: T520B227M2R5ATE015; Num Pins: 2; PART_SUBCLASS: CAPACITORS; RATED_VOLTAGE: 2.5V; RoHS Compliant: RoHS Compliant; TOLERANCE: 20%; Type: TANT POLY
C840-C842 C858 C859 C1208-C1210 C1212 C1236 C1241 C1321 C1341-C1344 C1361-C1364 C1384-C1387 C1405-C1408 C1423 C1430-C1433 = CAP: CAP CER 10UF 6.3V X6S 0603; AGILE_LINK: http://sj-agile9app/Agile/PLMServlet?action=OpenEmailObject&classid=10000&objid=257560276; IPN: K19402-001; Item Num: P03-17964R; LIFECYCLE_PHASE: Active; Lead Free Status: Not Lead Free; MFR_LIFECYCLE: Active; Manufacturer: TDK; Manufacturer Part Num: C1608X6S0J106M080AC; Num Pins: 2; PART_SUBCLASS: CAPACITORS; RATED_VOLTAGE: 6.3V; RoHS Compliant: RoHS Compliant; TOLERANCE: 20%; Temperature Coefficient: X6S
C860 C861 = CAP: CAP - CER, 4.7UF, 6.3V, X5R, 0603; AGILE_LINK: http://sj-agile9app/Agile/PLMServlet?action=OpenEmailObject&classid=10000&objid=257560276; IPN: G62544-001; Item Num: P03-16772R; LIFECYCLE_PHASE: Active; Lead Free Status: Not Lead Free; MFR_LIFECYCLE: Active; Manufacturer: Murata; Manufacturer Part Num: GRM188R60J475KE19D; Num Pins: 2; PART_SUBCLASS: CAPACITORS; RATED_VOLTAGE: 6.3V; RoHS Compliant: RoHS Compliant; TOLERANCE: +/-10%
C1196 C1197 C1242 C1243 C1298 C1299 C1302 C1303 C1315 C1323 C1324 C1367 C1388 = PCAP: CAP, POSCAP 220UF 6.3V 20% 15MOHM ESR, D2E CASE; IPN: 724613-066; Item Num: P03-18023R; LIFECYCLE_PHASE: Active; Lead Free Status: Lead Free; MFR_LIFECYCLE: Active; Manufacturer: Panasonic; Manufacturer Part Num: 6TPE220MI; Num Pins: 2; PART_SUBCLASS: CAPACITORS; RATED_VOLTAGE: 6.3V; RoHS Compliant: RoHS Compliant; Working Voltage: 6.3V
C679 C1199 C1200 C1213 C1222 C1227 C1424 C1425 C1428 C1429 = PCAP: CAP - POSCAP 100uF, 6.3V, ESR =.025 OHMS, B2; IPN: 724613-168; LIFECYCLE_PHASE: Active; Lead Free Status: Lead Free; MFR_LIFECYCLE: Active; Manufacturer: Panasonic; Manufacturer Part Num: 6TPE100MPB; Num Pins: 2; PART_SUBCLASS: CAPACITORS; RATED_VOLTAGE: 6.3V; RoHS Compliant: RoHS Compliant; Working Voltage: 6.3V
C1232-C1234 = CAP: CAPC,Y5V,0402,0.1UF,25V,+80/-20%; Dielectric: Y5V; IPN: K13560-001; Item Num: P03-15057R; LIFECYCLE_PHASE: Active; Lead Free Status: Lead Free; MFR_LIFECYCLE: Active; Manufacturer: Murata; Manufacturer Part Num: GRM155F51E104ZA01D; Num Pins: 2; PART_SUBCLASS: CAPACITORS; Part Class: CAPACITORS; RATED_VOLTAGE: 25V; RoHS Compliant: RoHS Compliant; Tolerance: +80%/-20%
C1244-C1246 = CAP: CAP CER 100UF 6.3V X5R 0805; AGILE_LINK: http://sj-agile9app/Agile/PLMServlet?action=OpenEmailObject&classid=10000&objid=257560276; IPN: K32109-001; Item Num: P03-17918R; LIFECYCLE_PHASE: Active; Lead Free Status: Lead Free; MFR_LIFECYCLE: Active; Manufacturer: Murata; Manufacturer Part Num: GRM21BR60J107ME15L; Num Pins: 2; PART_SUBCLASS: CAPACITORS; RATED_VOLTAGE: 6.3V; RoHS Compliant: RoHS Compliant; TOLERANCE: 20%; Temperature Coefficient: X6T
C1247 C1248 C1286-C1291 C1503-C1517 = CAP: CAP CER 22UF 6.3V X6S 0603; AGILE_LINK: http://sj-agile9app/Agile/PLMServlet?action=OpenEmailObject&classid=10000&objid=257560276; IPN: H63299-001; Item Num: P03-17963R; LIFECYCLE_PHASE: Active; Lead Free Status: Not Lead Free; MFR_LIFECYCLE: Active; Manufacturer: Murata; Manufacturer Part Num: GRM188C80J226ME15D; Num Pins: 2; PART_SUBCLASS: CAPACITORS; RATED_VOLTAGE: 6.3V; RoHS Compliant: RoHS Compliant; TOLERANCE: 20%; Temperature Coefficient: X6S
C1249 C1250 = CAP: CAP - 10µF 6.3V Ceramic Capacitor X5R 0402; AGILE_LINK: http://sj-agile9app/Agile/PLMServlet?action=OpenEmailObject&classid=10000&objid=257560276; IPN: A36096-114; Item Num: P03-17886R; LIFECYCLE_PHASE: Active; Lead Free Status: Not Lead Free; MFR_LIFECYCLE: Active; Manufacturer: MURATA; Manufacturer Part Num: GRM155R60J106ME44D; Num Pins: 2; PART_SUBCLASS: CAPACITORS; RATED_VOLTAGE: 6.3V; RoHS Compliant: RoHS Compliant; TOLERANCE: 20%; Temperature Coefficient: X6S
C1292-C1297 C1483-C1502 = CAP: CAP - CER 47UF, 10V, 20%, X5R, +/-20%, 0805; AGILE_LINK: http://sj-agile9app/Agile/PLMServlet?action=OpenEmailObject&classid=10000&objid=257560276; IPN: 644066-136; Item Num: P03-17686R; LIFECYCLE_PHASE: Active; Lead Free Status: Not Lead Free; MFR_LIFECYCLE: Active; Manufacturer: TDK Electronics; Manufacturer Part Num: C2012X5R1A476M125AC; Num Pins: 2; PART_SUBCLASS: CAPACITORS; RATED_VOLTAGE: 6.3V; RoHS Compliant: RoHS Compliant; TOLERANCE: 20%; Temperature Coefficient: X5R
C1309-C1314 C1330-C1339 C1350-C1359 C1373-C1382 C1394-C1403 = CAP: CAP CER 4.7UF 6.3V X5R 0201; IPN: K38116-001; Item Num: P03-17928R; Lead Free Status: Yes; Manufacturer: Murata; Manufacturer Part Num: GRM035R60J475ME15D; Num Pins: 2; Part Class: CAPACITORS; RoHS Compliant: Yes
C555 = CAP: CAP CER 22UF 6.3V X6S 0603; AGILE_LINK: http://sj-agile9app/Agile/PLMServlet?action=OpenEmailObject&classid=10000&objid=257560276; IPN: H63299-001; Item Num: P03-17963R; LIFECYCLE_PHASE: Active; Lead Free Status: Not Lead Free; MFR_LIFECYCLE: Active; Manufacturer: Murata; Manufacturer Part Num: GRM188C80J226ME15D; Num Pins: 2; PART_SUBCLASS: CAPACITORS; RATED_VOLTAGE: 6.3V; RoHS Compliant: RoHS Compliant; TOLERANCE: 20%; Temperature Coefficient: X6S; Working Voltage: 6.3V
C557 = CAP: CAP CER 47PF 50V C0G/NP0 0402; AGILE_LINK: http://sj-agile9app/Agile/PLMServlet?action=OpenEmailObject&classid=10000&objid=257560276; IPN: K19455-001; Item Num: P03-17996R; LIFECYCLE_PHASE: Active; Lead Free Status: Not Lead Free; MFR_LIFECYCLE: Active; Manufacturer: Murata; Manufacturer Part Num: GRM1555C1H470FA01D; Num Pins: 2; PART_SUBCLASS: CAPACITORS; RATED_VOLTAGE: 50V; RoHS Compliant: RoHS Compliant; TOLERANCE: 1%; Temperature Coefficient: C0G/NPO
C558-C560 = CAP: CAP CER 22UF 6.3V X6S 0603; AGILE_LINK: http://sj-agile9app/Agile/PLMServlet?action=OpenEmailObject&classid=10000&objid=257560276; IPN: H63299-001; Item Num: P03-17963R; LIFECYCLE_PHASE: Active; Lead Free Status: Lead Free; MFR_LIFECYCLE: Active; Manufacturer: Murata; Manufacturer Part Num: GRM188C80J226ME15D; Num Pins: 2; PART_SUBCLASS: CAPACITORS; RATED_VOLTAGE: 6.3V; RoHS Compliant: RoHS Compliant; TOLERANCE: 20%; Temperature Coefficient: X6S; Working Voltage: 6.3V
C561 = CAP: CAP - CER, 10NF, 50V, +/-10%, X7R, 0402 SMD; CAPACITANCE: 0.1uF; Dielectric: X7R; IPN: A36096-100; Item Num: P03-16318R; LIFECYCLE_PHASE: Active; Lead Free Status: Lead Free; Manufacturer: Murata; Manufacturer Part Num: GRM155R71H103KA88D; Num Pins: 2; Part Class: CAPACITORS; RATED_VOLTAGE: 50V; RoHS Compliant: RoHS Compliant; Tolerance: 10%
C1990 = CAP: CAP - CER, 1UF, 25V, 10%, X5R, 0402; IPN: H29050-001; IPN No: H29050-001; Item Num: P03-17662R; Lead Free Status: Yes; Manufacturer: TDK Electronics; Manufacturer Part Num: CGB2A1X5R1E105K033BC; Num Pins: 2; Part Class: CAPACITORS; RoHS Compliant: Yes; Voltage: 25V
C1991 C2037 = Cap,_NP,_1206: CAP - CER, 22UF, 25V, 10%, X5R, 1206; IPN: K28232-001; Item Num: P03-17640R; Manufacturer: Murata; Manufacturer Part Num: GRM31CR61E226KE15L; Voltage: 25V
C1992 C1993 = Cap,_NP,_1206: CAP - CER 47UF 10V 20% X5R 1206; IPN: K13655-001; Item Num: P03-17644R; Manufacturer: TDK Electronics; Manufacturer Part Num: C3216X5R1A476M160AB; Voltage: 10V
C2036 = Cap,_NP,_0402: CAPC,C0G,0402,100.000PF,50.000V,+/-5%; IPN: A36095-026; Item Num: P03-11677R; Manufacturer: Murata; Manufacturer Part Num: UMK105CG101JV-F; RATED_VOLTAGE: 50V; Voltage: 50V
C2038 = CAP: CAP - CER 4.7UF, +/-20%, 6.3V, X5R, 0402; IPN: H68701-001; Item Num: P03-17432R; Manufacturer: Murata; Manufacturer Part Num: GRM155R60J475ME87D; Tolerance: +/-20%; Voltage: 6.3V
FB33 = BEAD_FERRITE_SM: FERRITE BEAD 80 OHM 0805 1LN; IPN: G32678-001; Item Num: P04-17218R; LIFECYCLE_PHASE: Active; MFR_LIFECYCLE: Active; Manufacturer: Laird; Manufacturer Part Num: HI0805R800R-10; Num Pins: 2; PART_SUBCLASS: INDUCTORS; Part Class: Inductors; RoHS Compliant: Yes; Value2: 5A, 10mOhm
R546 = RESISTOR: RES SMD 4.02KOHM 1% 1/16W 0402; IPN: K15726-001; Item Num: P02-15351R; Lead Free Status: Yes; Manufacturer: Panasonic; Manufacturer Part Num: ERJ-2RKF4021x; Num Pins: 2; Part Class: RESISTORS; RoHS Compliant: Yes; TOLERANCE: 1%
R547 R669 R6060 R6083 = RESISTOR: RES ZERO OHM 1/16W 5% 0402 SMD; Altera Part No.: P02-14020R; IPN: H30887-001; Item Num: P02-14020R; Lead Free Status: No; Manufacturer: Panasonic; Manufacturer Part Num: ERJ-2GE0R00X; Num Pins: 2; Part Class: RESISTORS; Price: 0; RoHS Compliant: Yes; Tolerance: 5%
R548 = RESISTOR: RES - 1.54K OHM, 1/10W, 1%, 0402 SMD; IPN: A93548-114; Item Num: A93548-114; Lead Free Status: yes; Manufacturer: Yageo; Manufacturer Part Num: RC0402FR-071K54L; Num Pins: 2; Part Class: Resistors; TOLERANCE: 1%
R549 R671 R788 R830 R6062 R6085 = RESISTOR: RES 4.7K OHM 1/16W 5% 0402 SMD; IPN: H30885-001; Item Num: P02-14032R; Lead Free Status: No; Manufacturer: Panasonic; Manufacturer Part Num: ERJ-2GEJ472X; Manufacturer's Part No.: ERJ-2GEJ472X; Num Pins: 2; Part Class: RESISTORS; Price: 0; RoHS Compliant: Yes
R6055 R6058 R6065 R6066 R6079 = Resistor,_0402: RES,100K OHMS,1.0%,1/16W,0402; IPN: E86804-001; Item Num: P02-11386R; Manufacturer: Panasonic; Manufacturer Part Num: ERJ-2RKF1003X; POWER: 1/16W; TOLERANCE: +/-1%
R6067 = RES: RES 72.3K OHM 0.5% 1/10W 0402; IPN: M78387-001; Item Num: P02-15992R; Manufacturer: Vishay Dale; Manufacturer Part Num: TNPW040272K3DEED; Package: SMD; Part Class: RESISTORS; Type: Resistor
R6061 R6084 R6294 = RESISTOR: RES ZERO OHM 1/16W 5% 0402 SMD; Altera Part No.: P02-14020R; IPN: H30887-001; Item Num: P02-14020R; LIFECYCLE_PHASE: Active; Lead Free Status: No; MFR_LIFECYCLE: Active; Manufacturer: Panasonic; Manufacturer Part Num: ERJ-2GE0R00X; Num Pins: 2; PART_SUBCLASS: RESISTORS; POWER: 1/16W; Part Class: RESISTORS; RoHS Compliant: RoHS Compliant; Tolerance: +/-5%
ST15 ST17 = SHORT
U50 = EY1501di-adj: IC,LIN,DFN,ISL80101-AD,VREF; IPN: H38446-001; Item Num: P01-18061R; Manufacturer: Intel/Enpirion; Manufacturer Part Num: ISL80101IRAJZ-T
U66 = LTM4668IY#PBF: IPN: M85055-001
C680 = PCAP: CAP DNI 1210; AGILE_LINK: http://sj-agile9app/Agile/PLMServlet?action=OpenEmailObject&classid=10000&objid=14603863; LIFECYCLE_PHASE: Active; MFR_LIFECYCLE: Active; Num Pins: 2; PART_SUBCLASS: CAPACITORS
C681 = CAP_NP: CAP CER 47000PF 25V X7R 0402; AGILE_LINK: http://sj-agile9app/Agile/PLMServlet?action=OpenEmailObject&classid=10000&objid=215383831; CAPACITANCE: 47000pF; IPN: J98424-001; Item Num: P03-15072R; LIFECYCLE_PHASE: Preliminary; Manufacturer: Murata; Manufacturer Part Num: GRM155R71E473KA88D; Num Pins: 2; PART_SUBCLASS: CAPACITORS; RATED_VOLTAGE: 25V; TOLERANCE: +/-10%; Working Voltage: 25V
C1975 = CAP: CAP - CER, 1UF, 25V, 10%, X5R, 0402; IPN: H29050-001; Item Num: P03-17662R; Lead Free Status: Yes; Manufacturer: TDK Electronics; Manufacturer Part Num: CGB2A1X5R1E105K033BC; Num Pins: 2; Part Class: CAPACITORS; RoHS Compliant: Yes; Working Voltage: 25V
C1976 = CAP: CAP - CER, 1UF, 25V, 10%, X5R, 0402; IPN: H29050-001; IPN No: H29050-001; Item Num: P03-17662R; Lead Free Status: Yes; Manufacturer: TDK Electronics; Manufacturer Part Num: CGB2A1X5R1E105K033BC; Num Pins: 2; Part Class: CAPACITORS; RoHS Compliant: Yes; Working Voltage: 25V
C1977 C2001 = Cap,_NP,_1206: CAP - CER, 22UF, 25V, 10%, X5R, 1206; IPN: K28232-001; Item Num: P03-17640R; Manufacturer: Murata; Manufacturer Part Num: GRM31CR61E226KE15L; Working Voltage: 25V
C1978 = CAP: CAP CER 22PF 25V C0G/NP0 0402; AGILE_LINK: http://sj-agile9app/Agile/PLMServlet?action=OpenEmailObject&classid=10000&objid=257385742; CAPACITANCE: 12pF; IPN: J43675-001; Item Num: P03-15352R; LIFECYCLE_PHASE: Active; Lead Free Status: Lead Free; MFR_LIFECYCLE: Active; Manufacturer: Murata Electronics; Manufacturer Part Num: GRT1555C1E220JA02J; Num Pins: 2; PART_SUBCLASS: CAPACITORS; RATED_VOLTAGE: 50V; RoHS Compliant: RoHS Compliant; TOLERANCE: +/-5%; Working Voltage: 25V
C1979 = CAP: CAP - CER, 10NF, 50V, +/-10%, X7R, 0402 SMD; IPN: A36096-100; Item Num: P03-16318R; Manufacturer: Murata; Manufacturer Part Num: GRM155R71H103KA88D; Price: 0; RoHS Compliant: RoHS Compliant; Working Voltage: 50V
C1980 C1981 = Cap,_NP,_1206: CAP - CER 47UF 10V 20% X5R 1206; IPN: K13655-001; Item Num: P03-17644R; Manufacturer: TDK Electronics; Manufacturer Part Num: C3216X5R1A476M160AB; Working Voltage: 10V
C2033 = CAP: CAPC,C0G,0402,100.000PF,50.000V,+/-5%; CAPACITANCE: 100pF; Dielectric: X7R; IPN: A36095-026; IPN No: A36095-026; Item Num: P03-XXXXXR; LIFECYCLE_PHASE: Active; Lead Free Status: Lead Free; Manufacturer: AVX; Manufacturer Part Num: UMK105CG101JV-F; Num Pins: 2; Part Class: CAPACITORS; RATED_VOLTAGE: 50V; RoHS Compliant: RoHS Compliant; Tolerance: 10%; Working Voltage: 50V
R667 = RESISTOR_0603: RES - 0 OHM,  1206 1/2W; Device: R746; IPN: A93552-015; Manufacturer: Vishay Dale; Manufacturer Part Num: CRCW12060000Z0EAHP; Tolerance: 0.05
R668 = RESISTOR: RES ZERO OHM 1/16W 5% 0402 SMD; IPN: H30887-001; Item Num: P02-14020R; Lead Free Status: No; Manufacturer: Panasonic; Manufacturer Part Num: ERJ-2GE0R00X; Num Pins: 2; Part Class: RESISTORS; RoHS Compliant: Yes; Tolerance: 5%
R670 = RES_0_OHM_5%_1_16W_0402_SMD: IPN: H30887-001
R6056 = RESISTOR: RES,100K OHMS,1.0%,1/16W,0402; AGILE_LINK: http://sj-agile9app/Agile/PLMServlet?action=OpenEmailObject&classid=10000&objid=146932246; IPN: E86804-001; Item Num: P02-11386R; LIFECYCLE_PHASE: Active; MFR_LIFECYCLE: Active; Manufacturer: Panasonic; Manufacturer Part Num: ERJ-2RKF1003X; Num Pins: 2; PART_SUBCLASS: RESISTORS; POWER: 1/16W; RESISTANCE: 100K; RoHS Compliant: RoHS Compliant; TOLERANCE: +/-1%
R6057 = Resistor,_0402: RES,100K OHMS,1.0%,1/16W,0402; IPN: E86804-001; Item Num: P02-11386R; Manufacturer: Panasonic; Manufacturer Part Num: ERJ-2RKF1003X; POWER: 1/16W; RESISTANCE: 100K; TOLERANCE: +/-1%
R6059 = RESISTOR: RES ZERO OHM 1/16W 5% 0402 SMD; Altera Part No.: P02-14020R; IPN: H30887-001; Item Num: P02-14020R; LIFECYCLE_PHASE: Active; Lead Free Status: No; MFR_LIFECYCLE: Active; Manufacturer: Panasonic; Manufacturer Part Num: ERJ-2GE0R00X; Num Pins: 2; PART_SUBCLASS: RESISTORS; POWER: 1/16W; Part Class: RESISTORS; Price: 0; RESISTANCE: 0; RoHS Compliant: RoHS Compliant; Tolerance: +/-5%
R6063 = RES: RES SMD 19.1K OHM 1% 1/10W 0402; IPN: A93548-019; Item Num: P02-15992R; Manufacturer: Panasonic Electronic Components; Manufacturer Part Num: ERJ-2RKF1912X; Package: SMD; Part Class: RESISTORS; Type: Resistor
R6093 = RESISTOR: RES ZERO OHM 1/16W 5% 0402 SMD; Altera Part No.: P02-14020R; IPN: H30887-001; Item Num: P02-14020R; Lead Free Status: No; Manufacturer: Panasonic; Manufacturer Part Num: ERJ-2GE0R00X; Num Pins: 2; Part Class: RESISTORS; RoHS Compliant: Yes; Tolerance: 5%
TP38 TP39 = TP,_0.016_,_Thru_Hole
U61 = LTM4623EY#PBF: IPN: K15502-001
U62 = FDMC8878_VER2: MOSFET - N-CHANNEL Pwr Trench 40A 25V 3.5MOHM; IPN: K14521-001; Item Num: P18-31451R; Manufacturer: Fairchild Semiconductor; Manufacturer Part Num: FDMC2514SDC
U63 = LTC4365_DFN: IC,UV,OV,SUPPLY PROTECTION,,-1,3X2X0.75MM,-40C-125C; IPN: K13853-001; Item Num: P01-17742R; LIFECYCLE_PHASE: Active; Lead Free Status: Lead Free; MFR_LIFECYCLE: Active; Manufacturer: Linear Technology; Manufacturer Part Num: LTC4365CDDB-1#TRMPBF; Num Pins: 9; PART_SUBCLASS: ICS; RoHS Compliant: RoHS Compliant

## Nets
5V: R668.1 ; also on sheet 41 49 54
12V_G2: C1976.2 C1977.2 C1990.2 C1991.2 C2001.2 C2037.2 U61.C5(SVIN) U61.D5(VIN1) U61.E5(VIN2) U66.A4(VIN1) U66.B4(VIN2) U66.F4(VIN3) U66.G4(VIN4) ; also on sheet 45 48 49 50 54 55 57 60 61
GND: C293.2 C555.2 C558.2 C559.2 C560.2 C561.2 C679.2 C680.2 C681.2 C737.2 C762.2 C763.2 C764.2 C765.2 C766.2 C767.2 C768.2 C769.2 C770.2 C771.2 C772.2 C773.2 C774.2 C775.2 C776.2 C777.2 C778.2 C779.2 C780.2 C781.2 C782.2 C783.2 C784.2 C785.2 C786.2 C787.2 C788.2 C789.2 C790.2 C791.2 C792.2 C793.2 C794.2 C795.2 C796.2 C797.2 C798.2 C799.2 C800.2 C801.2 C802.1 C803.1 C804.1 C805.1 C806.1 C807.1 C808.2 C809.2 C810.2 C811.2 C812.2 C814.2 C815.2 C817.2 C818.2 C819.2 C821.2 C825.2 C828.2 C829.2 C830.2 C831.2 C832.2 C833.2 C834.2 C835.2 C836.2 C837.2 C838.2 C839.2 C840.1 C841.1 C842.1 C843.2 C844.2 C845.2 C846.2 C847.2 C848.2 C849.2 C850.2 C851.2 C852.2 C853.2 C854.2 C855.2 C856.2 C857.2 C858.1 C859.1 C860.2 C861.2 C1196.2 C1197.2 C1199.2 C1200.2 C1203.2 C1204.2 C1205.2 C1206.2 C1207.2 C1208.1 C1209.1 C1210.1 C1211.2 C1212.1 C1213.2 C1214.2 C1215.2 C1216.2 C1217.2 C1218.2 C1222.2 C1223.2 C1224.2 C1225.2 C1227.2 C1228.2 C1229.2 C1230.2 C1231.2 C1232.2 C1233.2 C1234.2 C1235.2 C1236.1 C1237.2 C1238.2 C1239.2 C1240.2 C1241.1 C1242.2 C1243.2 C1244.1 C1245.1 C1246.1 C1247.1 C1248.1 C1249.1 C1250.1 C1251.2 C1252.2 C1253.2 C1254.2 C1255.2 C1256.2 C1257.2 C1258.2 C1259.2 C1260.2 C1261.2 C1262.2 C1263.2 C1264.2 C1265.2 C1266.2 C1267.2 C1268.2 C1269.2 C1270.2 C1271.2 C1272.2 C1273.2 C1274.2 C1275.2 C1276.2 C1277.2 C1278.2 C1279.2 C1280.2 C1281.2 C1282.2 C1283.2 C1284.2 C1285.2 C1286.1 C1287.1 C1288.1 C1289.1 C1290.1 C1291.1 C1292.1 C1293.1 C1294.1 C1295.1 C1296.1 C1297.1 C1298.2 C1299.2 C1302.2 C1303.2 C1304.2 C1305.2 C1306.2 C1307.2 C1308.2 C1309.2 C1310.2 C1311.2 C1312.2 C1313.2 C1314.2 C1315.2 C1317.2 C1318.2 C1319.2 C1320.2 C1321.1 C1323.2 C1324.2 C1325.2 C1326.2 C1327.2 C1328.2 C1329.2 C1330.2 C1331.2 C1332.2 C1333.2 C1334.2 C1335.2 C1336.2 C1337.2 C1338.2 C1339.2 C1340.2 C1341.1 C1342.1 C1343.1 C1344.1 C1345.2 C1346.2 C1347.2 C1348.2 C1349.2 C1350.2 C1351.2 C1352.2 C1353.2 C1354.2 C1355.2 C1356.2 C1357.2 C1358.2 C1359.2 C1360.2 C1361.1 C1362.1 C1363.1 C1364.1 C1365.2 C1366.2 C1367.2 C1368.2 C1369.2 C1370.2 C1371.2 C1372.2 C1373.2 C1374.2 C1375.2 C1376.2 C1377.2 C1378.2 C1379.2 C1380.2 C1381.2 C1382.2 C1383.2 C1384.1 C1385.1 C1386.1 C1387.1 C1388.2 C1389.2 C1390.2 C1391.2 C1392.2 C1393.2 C1394.2 C1395.2 C1396.2 C1397.2 C1398.2 C1399.2 C1400.2 C1401.2 C1402.2 C1403.2 C1404.2 C1405.1 C1406.1 C1407.1 C1408.1 C1421.2 C1422.2 C1423.1 C1424.2 C1425.2 C1428.2 C1429.2 C1430.1 C1431.1 C1432.1 C1433.1 C1434.2 C1435.2 C1436.2 C1437.2 C1438.2 C1439.2 C1483.1 C1484.1 C1485.1 C1486.1 C1487.1 C1488.1 C1489.1 C1490.1 C1491.1 C1492.1 C1493.1 C1494.1 C1495.1 C1496.1 C1497.1 C1498.1 C1499.1 C1500.1 C1501.1 C1502.1 C1503.1 C1504.1 C1505.1 C1506.1 C1507.1 C1508.1 C1509.1 C1510.1 C1511.1 C1512.1 C1513.1 C1514.1 C1515.1 C1516.1 C1517.1 C1975.1 C1977.1 C1980.2 C1981.2 C1990.1 C1991.1 C1992.2 C1993.2 C2001.1 C2037.1 C2038.2 R548.2 R549.1 R671.1 R6062.1 R6066.1 R6085.1 ST15.2 ST17.2 U50.5(GND) U50.11(EPAD) U61.B3(GND) U61.C3(GND) U61.D3(GND) U61.D4(GND) U61.E3(GND) U63.1(GND) U63.2(OV) U63.9(GND) U66.A2(GND) U66.A3(GND) U66.A5(GND) U66.A6(GND) U66.B2(GND) U66.B3(GND) U66.B5(GND) U66.B6(GND) U66.C2(GND) U66.C6(GND) U66.D3(GND) U66.D4(GND) U66.D5(GND) U66.E2(GND) U66.E6(GND) U66.F2(GND) U66.F3(GND) U66.F5(GND) U66.F6(GND) U66.G2(GND) U66.G3(GND) U66.G5(GND) U66.G6(GND) ; also on sheet 9 11 12 13 14 15 17 18 20 21 22 23 24 25 26 28 29 30 31 32 34 35 36 37 38 39 40 41 42 43 44 45 46 47 48 49 50 51 52 53 54 55 56 57 58 59 60 61 62
VCCA_PLL_FLTR: C1216.1 C1217.1 C1218.1 C1222.1 C1223.1 C1224.1 C1225.1 C1319.1 C1320.1 C1321.2 ; also on sheet 34 45
VCCFUSEWR_EN: R547.1 R549.2 U50.7(EN) ; also on sheet 46
VCCFUSEWR_PG: R788.1 U50.4(POK) ; also on sheet 46
VCCFUSEWR_SDM: C293.1 C557.2 C558.1 C559.1 C560.1 C1235.1 R546.2 U50.1(VOUT1) U50.2(VOUT2) ; also on sheet 34
VCCH_GXER1_AGND: R6294.1 ST17.1
VCCH_GXER1_EN: R6084.2 ; also on sheet 46
VCCH_GXER1_PG: R6079.1 U66.D2(PGOOD1) ; also on sheet 46
VCCH_GXPL1: C1227.1 C1228.1 C1229.1 C1230.1 C1231.1 C1232.1 C1233.1 C1234.1 ; also on sheet 34
0p8V_VCCL_SDM: C737.1 C836.1 C837.1 C838.1 C839.1 C840.2 C841.2 C842.2 C1213.1 ; also on sheet 34 46 55
0p9V_VCCH: C1256.1 C1257.1 C1258.1 C1259.1 C1260.1 C1261.1 C1262.1 C1263.1 C1264.1 C1265.1 C1266.1 C1267.1 C1268.1 C1269.1 C1270.1 C1271.1 C1272.1 C1273.1 C1274.1 C1275.1 C1276.1 C1277.1 C1278.1 C1279.1 C1280.1 C1281.1 C1282.1 C1283.1 C1284.1 C1285.1 C1286.2 C1287.2 C1288.2 C1289.2 C1290.2 C1291.2 C1292.2 C1293.2 C1294.2 C1295.2 C1296.2 C1297.2 C1298.1 C1299.1 C1302.1 C1303.1 C1317.1 C1318.1 ; also on sheet 34 46 58
0p9V_VCCL_HPS: C828.1 C829.1 C830.1 C831.1 C832.1 C833.1 C834.1 C835.1 ; also on sheet 34 46 56
0p9V_VCCRT_GXER1: C843.1 C844.1 C845.1 C846.1 C847.1 C848.1 C849.1 C850.1 C851.1 C852.1 C853.1 C854.1 C855.1 C856.1 C857.1 C858.2 C859.2 C860.1 C861.1 C1196.1 C1197.1 C1199.1 C1200.1 ; also on sheet 34 58
0p9V_VCCRT_GXPL1: C1304.1 C1305.1 C1306.1 C1307.1 C1308.1 C1309.1 C1310.1 C1311.1 C1312.1 C1313.1 C1314.1 C1315.1 ; also on sheet 34 58
1p1V_VCCH_GXER1: C1242.1 C1243.1 C1244.2 C1245.2 C1246.2 C1247.2 C1248.2 C1249.2 C1250.2 C1251.1 C1252.1 C1253.1 C1254.1 C1255.1 C1992.1 C1993.1 C2036.1 U66.A1(VOUT1_1) U66.A7(VOUT2_1) U66.B1(VOUT1_2) U66.B7(VOUT2_2) U66.F1(VOUT4_1) U66.F7(VOUT3_1) U66.G1(VOUT4_2) U66.G7(VOUT3_2) ; also on sheet 34 46
1p2V_DDR4_CH01: C1323.1 C1324.1 C1325.1 C1326.1 C1327.1 C1328.1 C1329.1 C1330.1 C1331.1 C1332.1 C1333.1 C1334.1 C1335.1 C1336.1 C1337.1 C1338.1 C1339.1 C1340.1 C1341.2 C1342.2 C1343.2 C1344.2 C1345.1 C1346.1 C1347.1 C1348.1 C1349.1 C1350.1 C1351.1 C1352.1 C1353.1 C1354.1 C1355.1 C1356.1 C1357.1 C1358.1 C1359.1 C1360.1 C1361.2 C1362.2 C1363.2 C1364.2 C1365.1 C1366.1 ; also on sheet 9 12 13 34 40 42 46 60 62
1p2V_DDR4_CH23: C1367.1 C1368.1 C1369.1 C1370.1 C1371.1 C1372.1 C1373.1 C1374.1 C1375.1 C1376.1 C1377.1 C1378.1 C1379.1 C1380.1 C1381.1 C1382.1 C1383.1 C1384.2 C1385.2 C1386.2 C1387.2 C1388.1 C1389.1 C1390.1 C1391.1 C1392.1 C1393.1 C1394.1 C1395.1 C1396.1 C1397.1 C1398.1 C1399.1 C1400.1 C1401.1 C1402.1 C1403.1 C1404.1 C1405.2 C1406.2 C1407.2 C1408.2 ; also on sheet 15 16 18 19 25 34 46 61 62
1p2V_VCCR: C1428.1 C1429.1 C1430.2 C1431.2 C1432.2 C1433.2 C1434.1 C1435.1 C1436.1 C1437.1 C1438.1 C1439.1 ; also on sheet 34 59
1p8V: C1203.1 C1204.1 C1205.1 C1206.1 C1207.1 C1208.2 C1209.2 C1210.2 C1211.1 C1212.2 C1214.1 C1215.1 C1239.1 C1240.1 C1241.2 ; also on sheet 22 34 46 54
2p5V: C1980.1 C1981.1 C2033.2 U61.C1(VOUT1) U61.D1(VOUT2) U61.D2(VOUT3) U61.E1(VOUT4) U61.E2(VOUT5) ; also on sheet 9 12 15 18 21 34 38
2p5V_AGND: C1976.1 C1978.1 C1979.1 R6059.1 R6063.1 ST15.1 U61.B4(SGND)
2p5V_EN: R6061.2 ; also on sheet 46
2p5V_PG: R6055.1 U61.C2(PGOOD) ; also on sheet 46
3p3V: FB33.1 R547.2 R667.1 R669.2 R788.2 R6055.2 R6060.2 R6079.2 R6083.2 U62.5(D) U63.3(UV) ; also on sheet 46 50 51 54 55 56 57 58 59 60 61 62
FPGA_VCC: C762.1 C763.1 C764.1 C765.1 C766.1 C767.1 C768.1 C769.1 C770.1 C771.1 C772.1 C773.1 C774.1 C775.1 C776.1 C777.1 C778.1 C779.1 C780.1 C781.1 C782.1 C783.1 C784.1 C785.1 C786.1 C787.1 C788.1 C789.1 C790.1 C791.1 C792.1 C793.1 C794.1 C795.1 C796.1 C797.1 C798.1 C799.1 C800.1 C801.1 C802.2 C803.2 C804.2 C805.2 C806.2 C807.2 C808.1 C809.1 C810.1 C811.1 C812.1 C814.1 C815.1 C817.1 C818.1 C819.1 C821.1 C825.1 C1483.2 C1484.2 C1485.2 C1486.2 C1487.2 C1488.2 C1489.2 C1490.2 C1491.2 C1492.2 C1493.2 C1494.2 C1495.2 C1496.2 C1497.2 C1498.2 C1499.2 C1500.2 C1501.2 C1502.2 C1503.2 C1504.2 C1505.2 C1506.2 C1507.2 C1508.2 C1509.2 C1510.2 C1511.2 C1512.2 C1513.2 C1514.2 C1515.2 C1516.2 C1517.2 ; also on sheet 33 46 52 53
IO_1p8V: C1236.2 C1237.1 C1238.1 C1421.1 C1422.1 C1423.2 C1424.1 C1425.1 ; also on sheet 26 28 29 30 31 34 38 39 40 46 57
IO_3p3V: C679.1 C680.1 R667.2 U62.1(S1) U62.2(S2) U62.3(S3) U63.6(VOUT) ; also on sheet 12 23 24 25 28 30 31 38 39 40 41 42
IO_3p3V_EN: R670.2 ; also on sheet 46
LTM4623_INTVCC1: C1975.2 R6093.1 U61.E4(INTVCC)
LTM4668_INTVCC1: C2038.1 R6065.2 U66.C4(INTVCC) U66.C7(FB2) U66.E1(FB4) U66.E7(FB3)
MODE/SYNC1: R6065.1 R6066.2 U66.E4(MODE/SYNC)
N36348634: R830.1 U62.4(G) U63.5(GATE)
N36348657: R668.2 U63.4(VIN)
N36348739: R669.1 R670.1 R671.2 U63.8(~{SHDN})
N37269586: C555.1 FB33.2 U50.9(VIN1) U50.10(VIN2)
N37269687: C557.1 R546.1 R548.1 U50.3(VFB)
N37269689: C561.1 U50.6(SS)
N40909775: TP38.1 U61.B5(CLKOUT)
N40909802: TP39.1 U61.A5(CLKIN)
N40909854: R6056.2 R6057.2 R6058.2 R6093.2
N40909931: C1978.2 R6056.1 U61.A1(COMP)
N40909962: R6057.1 U61.B2(PHMODE)
N40909984: R6058.1 U61.C4(MODE)
N40910010: R6059.2 U61.A4(FREQ)
N40910028: C1979.2 U61.A2(TRACK/SS)
N40910038: R6060.1 R6061.1 R6062.2 U61.A3(RUN)
N40910129: C2033.1 R6063.2 U61.B1(FB)
N40980036: C2036.2 R6067.2 U66.C1(FB1)
N40980113: R6083.1 R6084.1 R6085.2 U66.C3(RUN1) U66.C5(RUN2) U66.E3(RUN4) U66.E5(RUN3)
N42653158: C681.1 R830.2
N43346477: R6067.1 R6294.2

Not connected (* = marked no-connect by the designer): U50 8(NC)*; U63 7(~{FAULT})*; U66 D1(PGOOD4)* D6(PGOOD2)* D7(PGOOD3)*

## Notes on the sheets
sheet 63
- PWR - 2p5V
- VIN  : 12V
- VOUT : 2p5V
- FSW  : 1MHz
- Tj   : -40 C TO 125 C
- ILOAD : 3A
- RFB=60.4K x (0.6/Vout-06)
- X5R
- X5R
- 1206
- 1206
- Connect the input
  cap to the GND plane
  through multiple vias.
  (see the Gerber files)
- Connect the output
  cap to the GND plane
  through multiple vias
- AGND
- PGND
- PLACE Output decoupling caps
  close to the device.  Connect
  AGND and PGND at the point of
  cap GND connection.
- 3.3V Enable Circuit
sheet 64
- PWR - 1p1V VCCH_GXER1
              VCCFUSEWR_SDM
- Connect the input
  cap to the GND plane
  through multiple vias.
- Connect the output
  cap to the GND plane
  through multiple vias
- VIN  : 12V
- VOUT : 1p1V
- FSW  : 1MHz
- Tj   : -40 C TO 125 C
- ILOAD : 4A
- RFB=60.4K x (0.6/Vout-06)
- AGND
- PGND
- PLACE Output decoupling caps
  close to the device.  Connect
  AGND and PGND at the point of
  cap GND connection.
- VDOmax = 185mV
- 1.8V
- Vout = 0.5V x (Rup/Rdn + 1)
- VINabsmax = -0.3V to 6.5V
- Rup
- Rdn
sheet 65
- Decoupling - page 1
- Place near FB17 and FB18
- Place under FPGA
- C1232 ~ C1234 are 0402
- 1 100uF + 1 10uF near to FPGA HPS area, 1 100uF+1 10uF near to FPGA SDM area
sheet 66
- Decoupling - page 2
sheet 67
- RE-SPIN CHANGES LIST FROM REV B0 TO REV C0
- Sr.No
- PAGE NO
- REF DES
- OLD IC  NUMBER
- NEW IC NUMER
- 1
- 50
- U46
- EM2130H01QI
- LTC7151
- 2
- 51
- U47
- ED8401P01QJ
- LTC3888IUHG-1#PBF
- 3
- 52
- U76
- ET6160LI
- LTC7051AV#PBF
- 4
- 52
- U77
- ET6160LI
- LTC7051AV#PBF
- 5
- 53
- U78
- ET6160LI
- LTC7051AV#PBF
- 6
- 53
- U79
- ET6160LI
- LTC7051AV#PBF
- 7
- 53
- U124
- ER3105DI
- LTM4622EV#PBF
- 8
- 54
- U71
- EM2120H01QI
- LTM4686EV-1
- 9
- 55
- U51
- EN6337QI
- LTM4623EY#PBF
- 10
- 56
- U65
- EN6362QI
- LTM4608AEV#PBF
- 11
- 57
- U70
- EN6347QI
- LTM4668IY#PBF
- 12
- 58
- U55
- EM2140P01QJ
- LTM4678EY#PBF
- 13
- 59
- U56
- EN6362QI
- LTM4608AEV#PBF
- 14
- 60
- U57
- EN63A0QI
- LTM4643EY#PBF
- 15
- 61
- U58
- EN63A0QI
- LTM4643EY#PBF
- 16
- 63
- U61
- EN6337QI
- LTM4623EY#PBF
- 17
- 64
- U66
- EN6347QI
- LTM4668IY#PBF
- 18
- 45
- U125
- LTM4657EY
- Input voltage changed to 12V
- 19
- 50
- U126
- INA219AIDCNR
- 20
- 43
- J14
- 0702461004
- REV B1 CHANGES
- 21
- 57,64
- U66, U70
- IC LTM4668IY#PBF U66, U70 PGood 2,3,4 pins are made it NC
- J22 connector modified from 2*5 to  2*2
- 22
- 51
- J22
- TP17, TP16 reused to LTM3888_ALERTn & FPGA_VCC_EN
- 23
- 51
- J22
- 24
- 51
- J22
- TP20 smd test point added to FPGA_VCC_PG
